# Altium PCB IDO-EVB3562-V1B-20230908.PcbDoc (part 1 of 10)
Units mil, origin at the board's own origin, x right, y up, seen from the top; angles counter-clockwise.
Board outline 5314.96 x 3543.31 mil, 4 copper layers (TOP, L2-VCC, L3-GND, BOTTOM), stack 28.8 mil thick; 747 components, 560 nets, 2514 pads, 1964 vias.
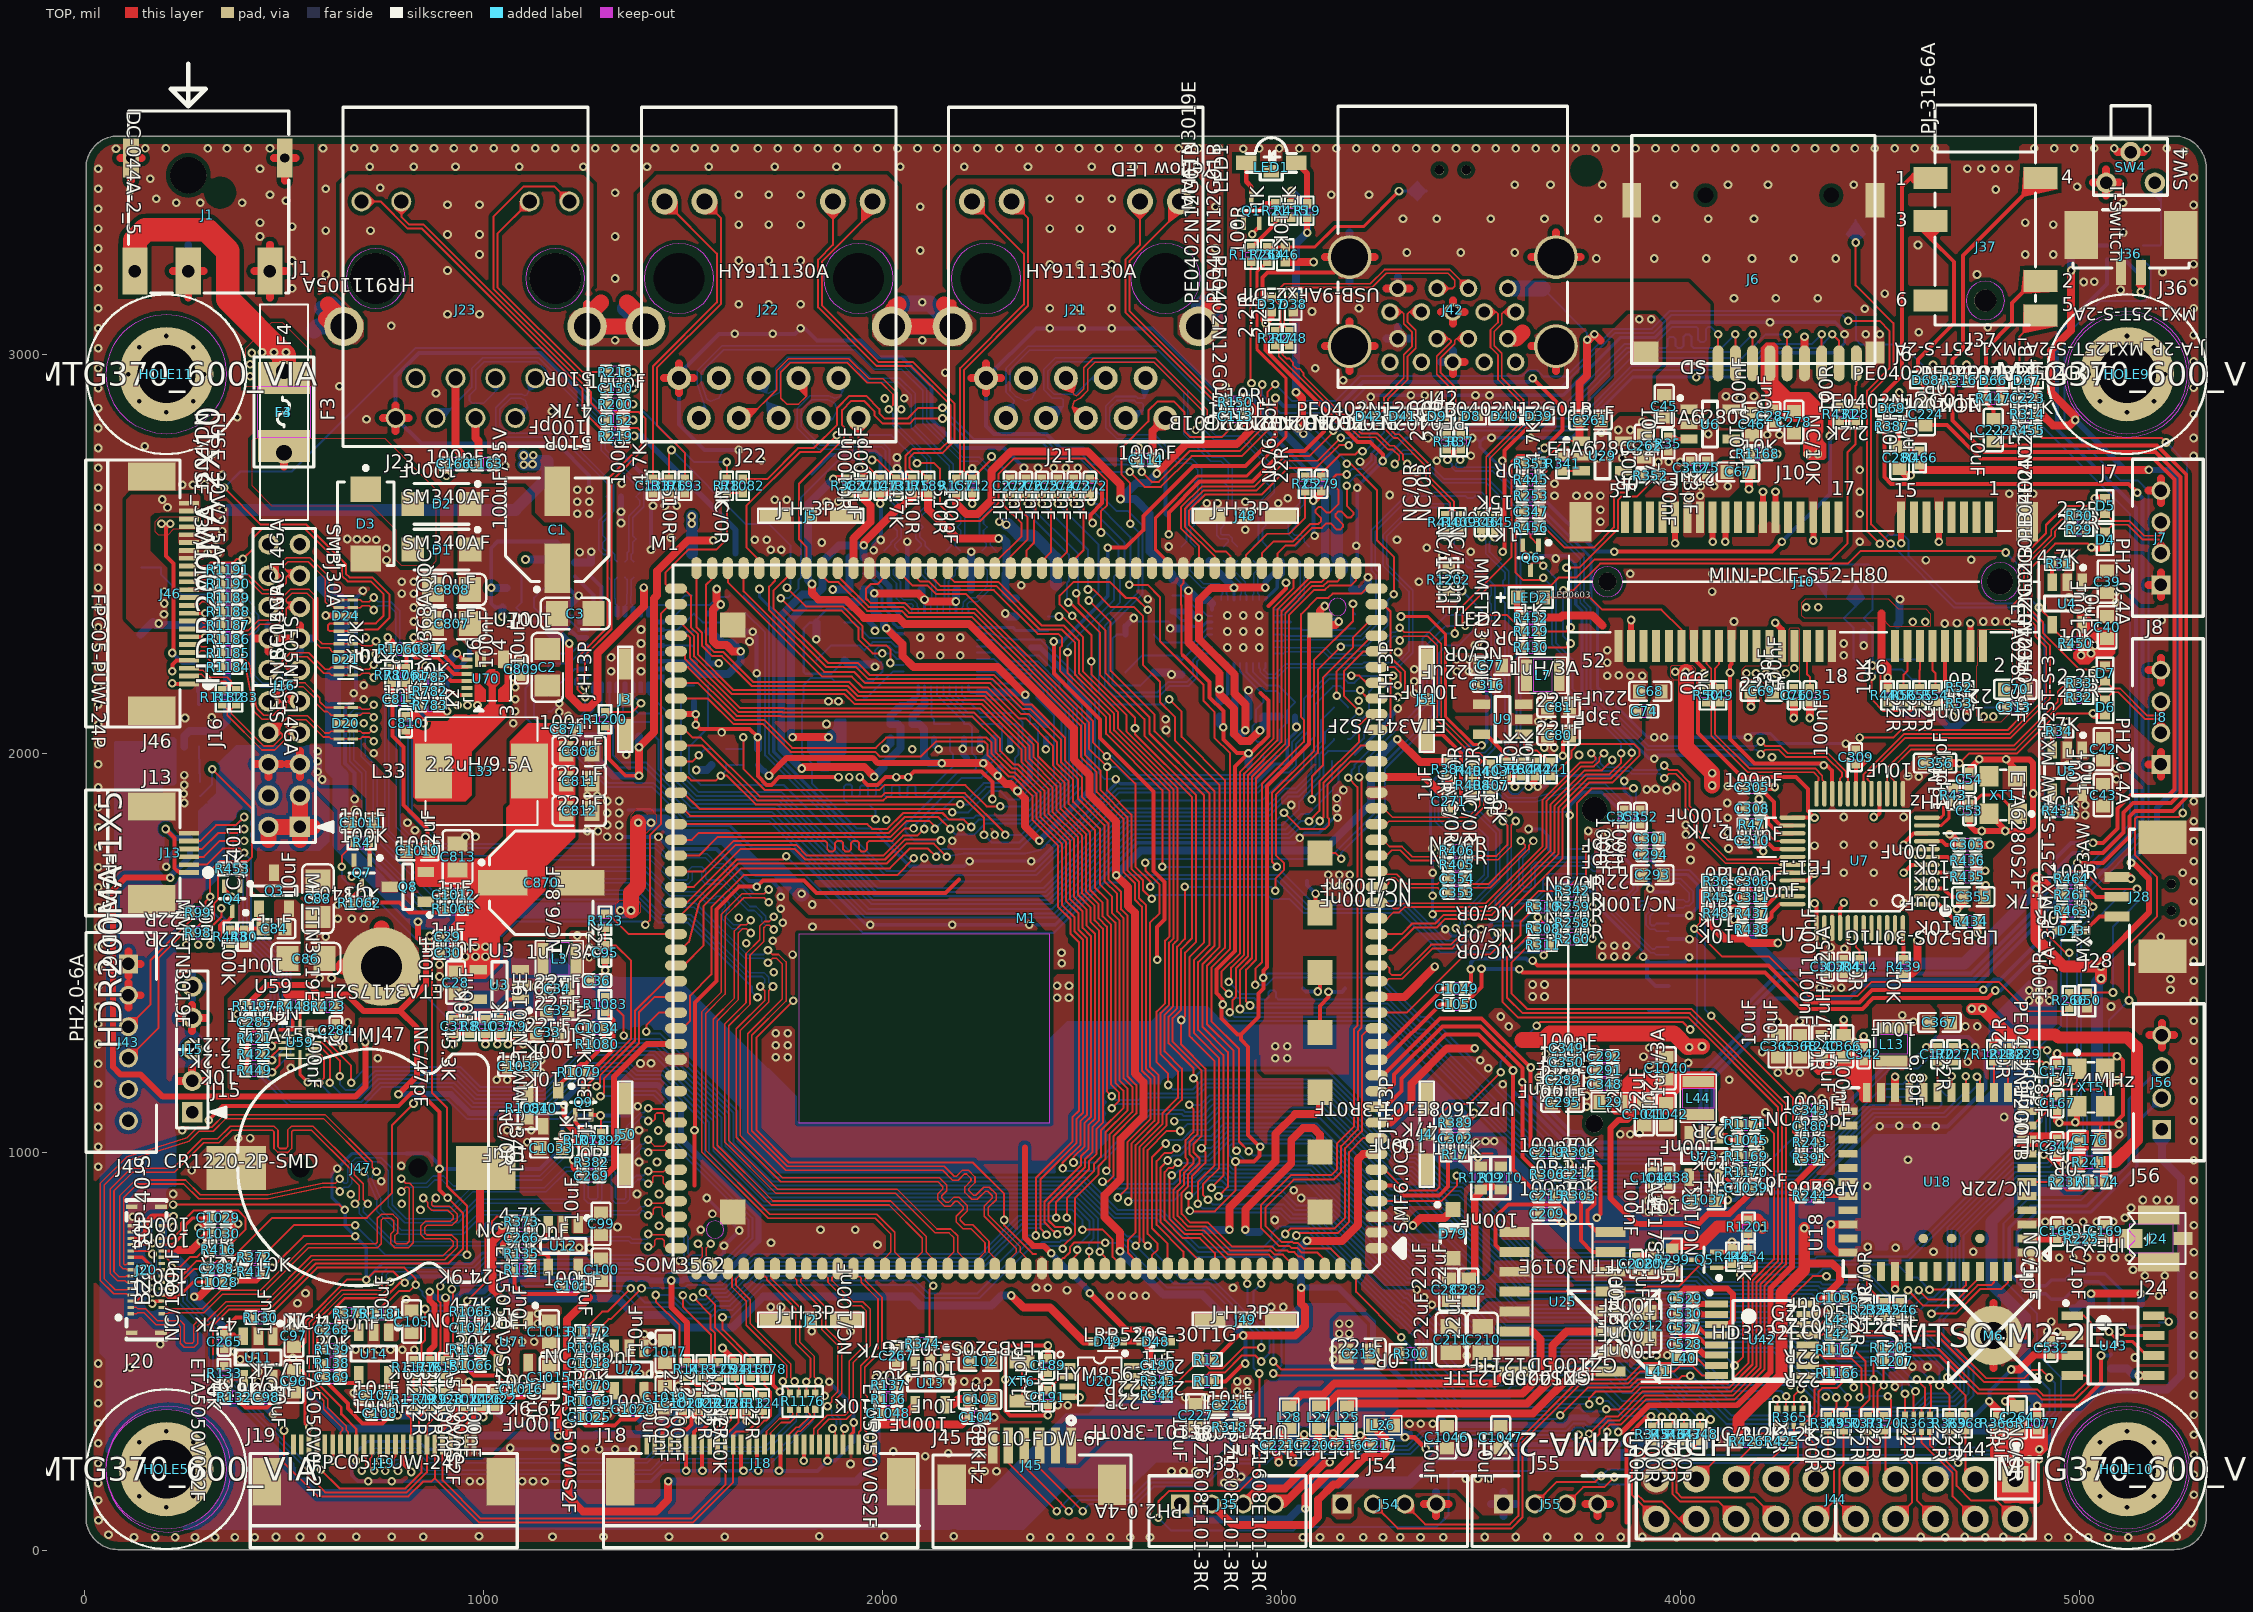
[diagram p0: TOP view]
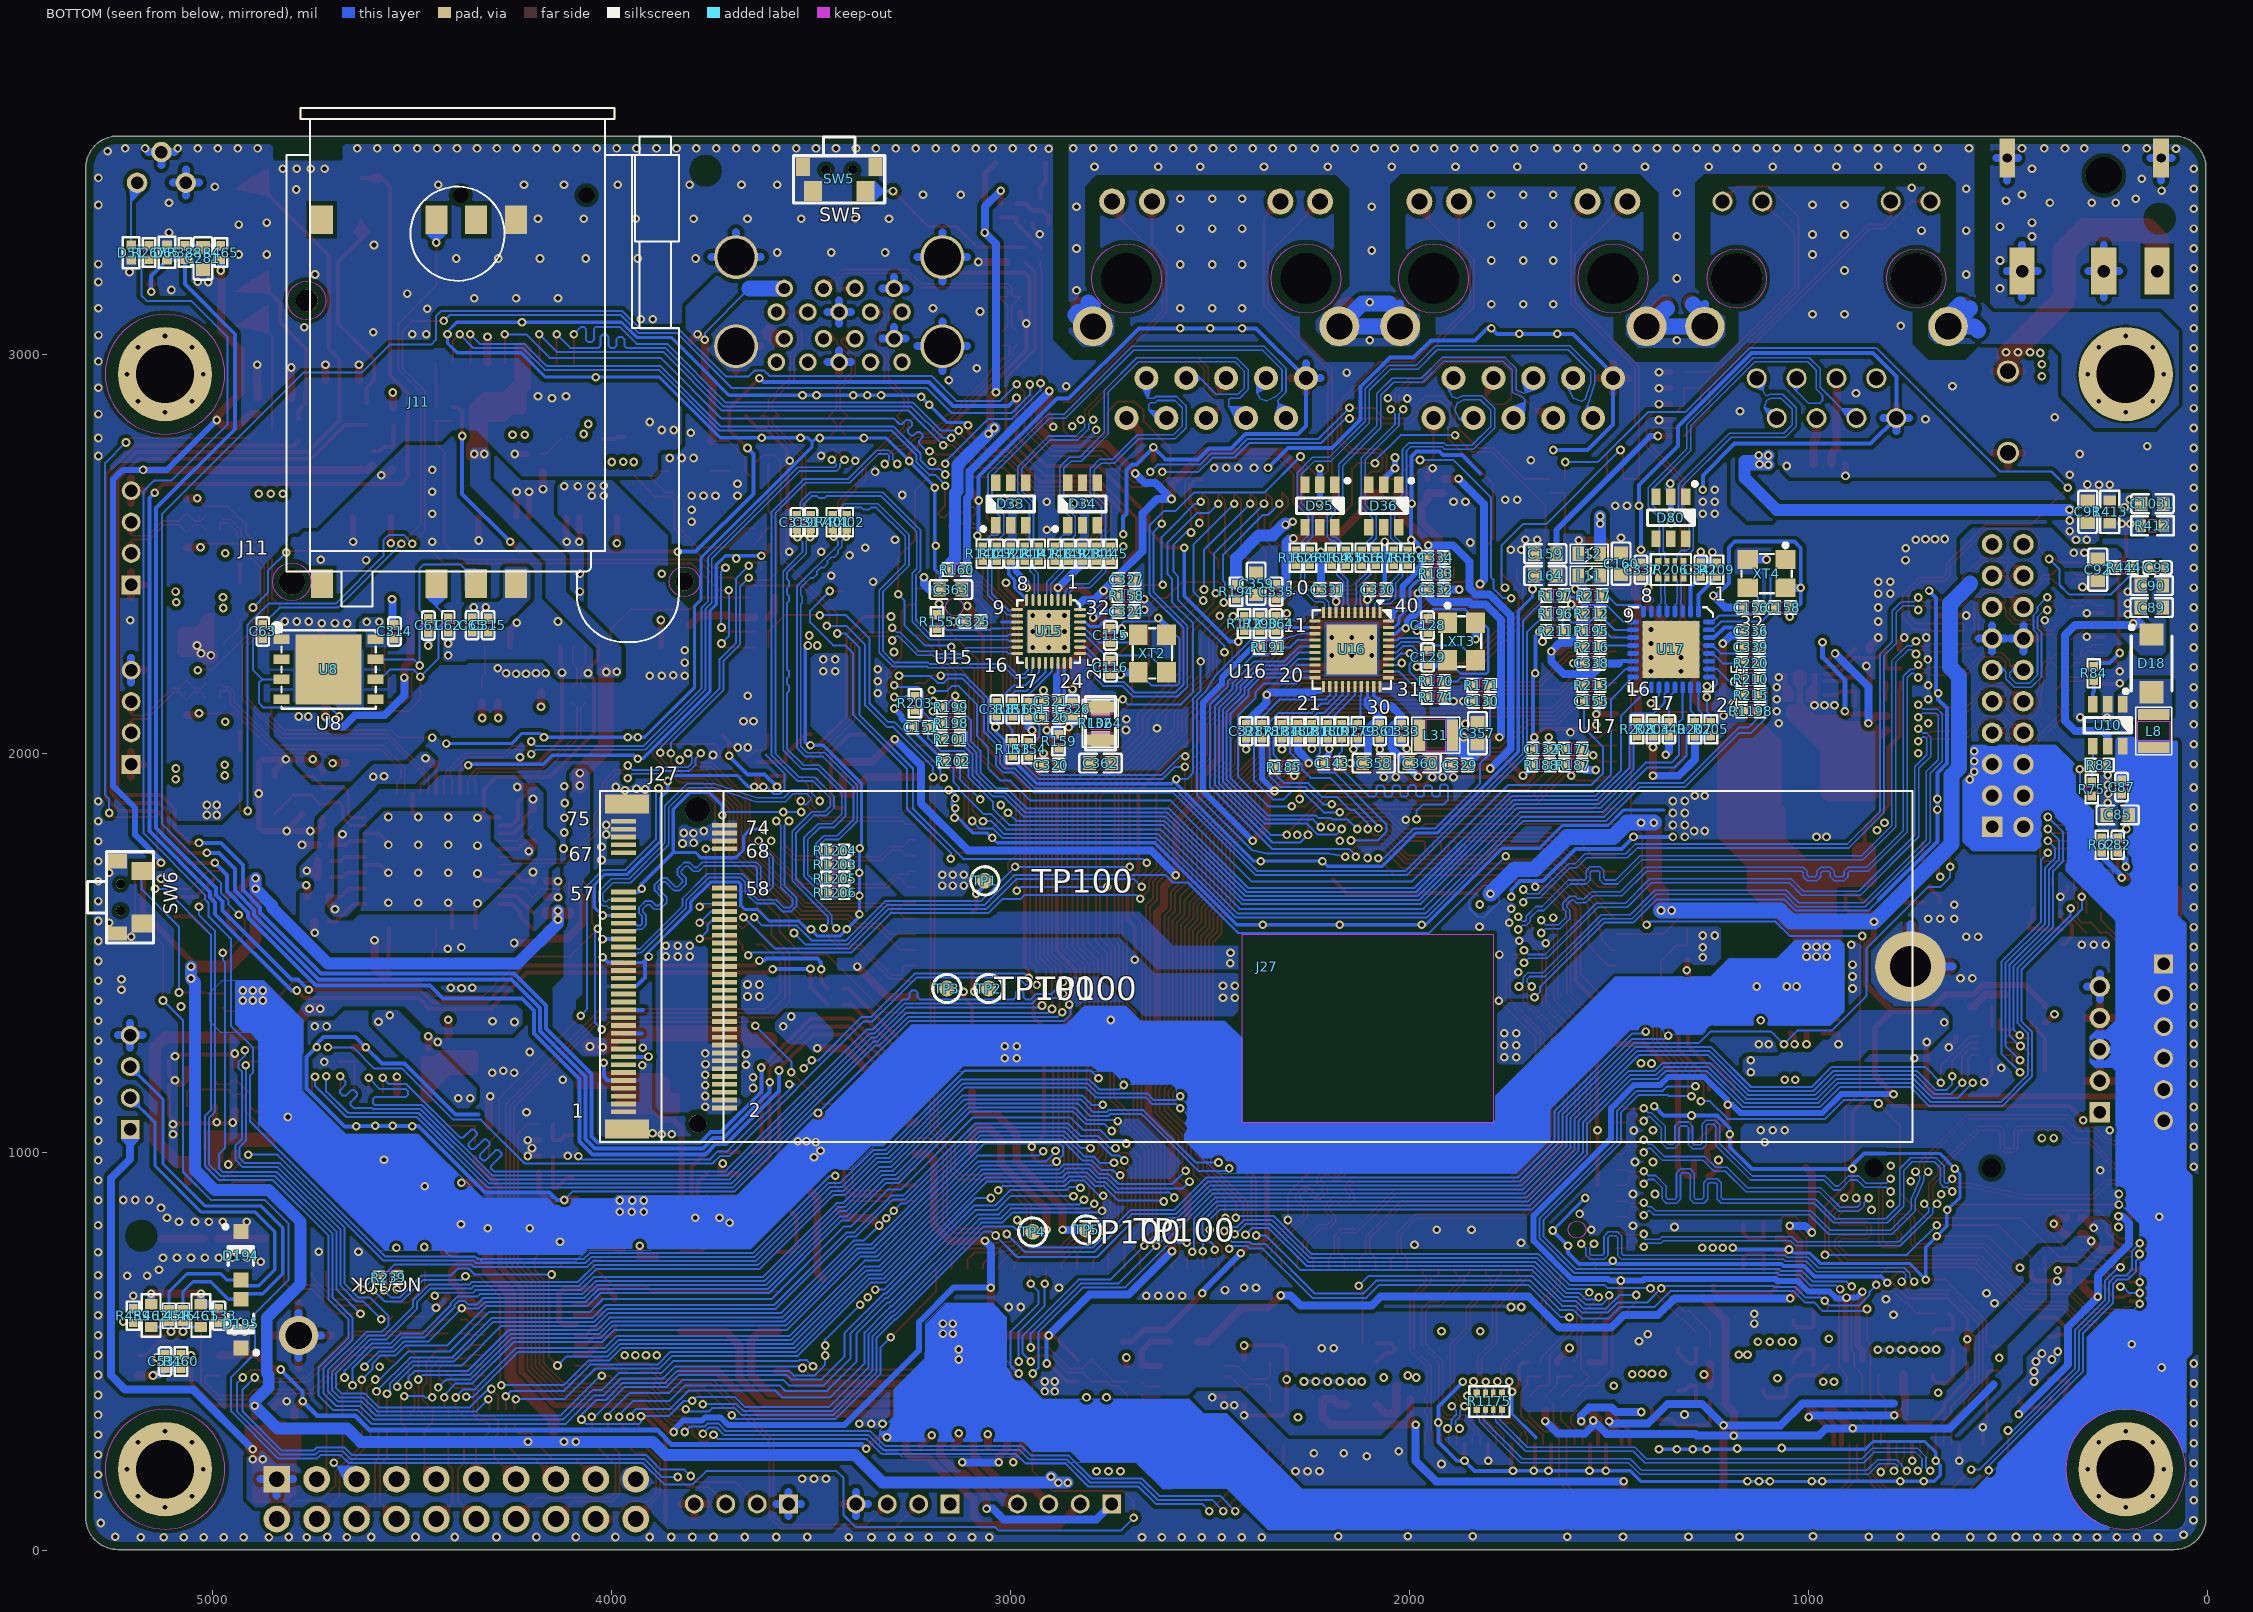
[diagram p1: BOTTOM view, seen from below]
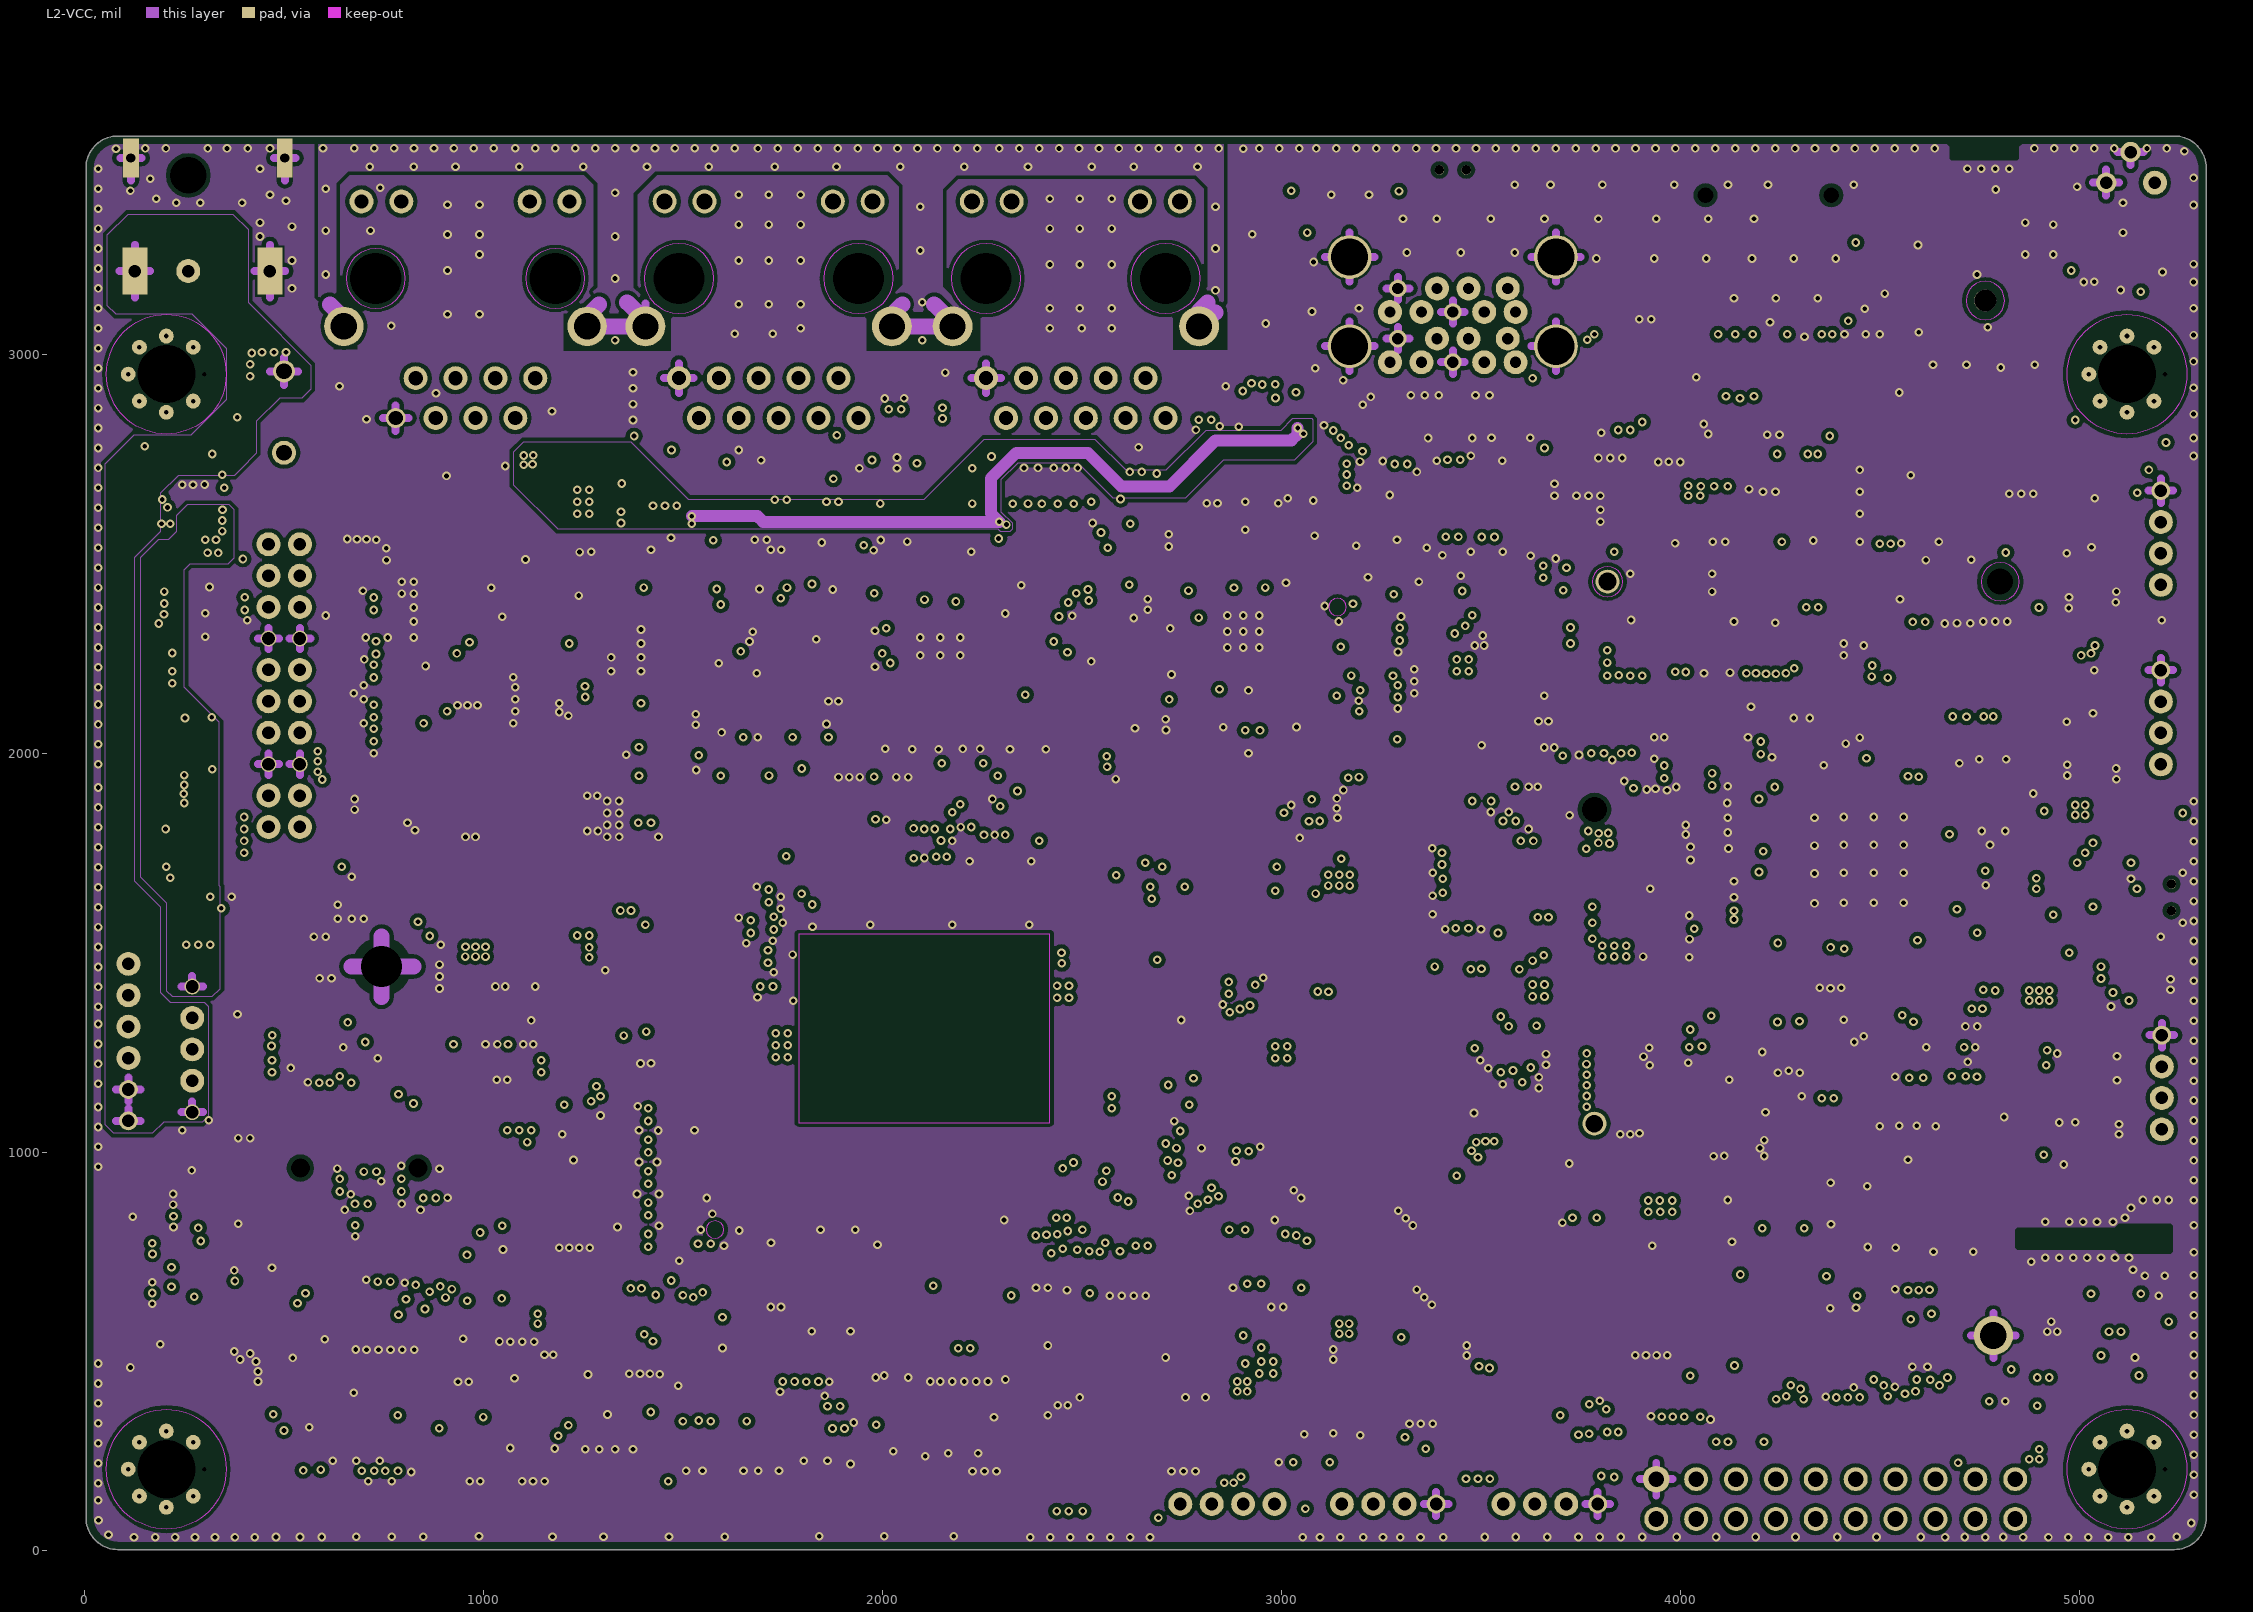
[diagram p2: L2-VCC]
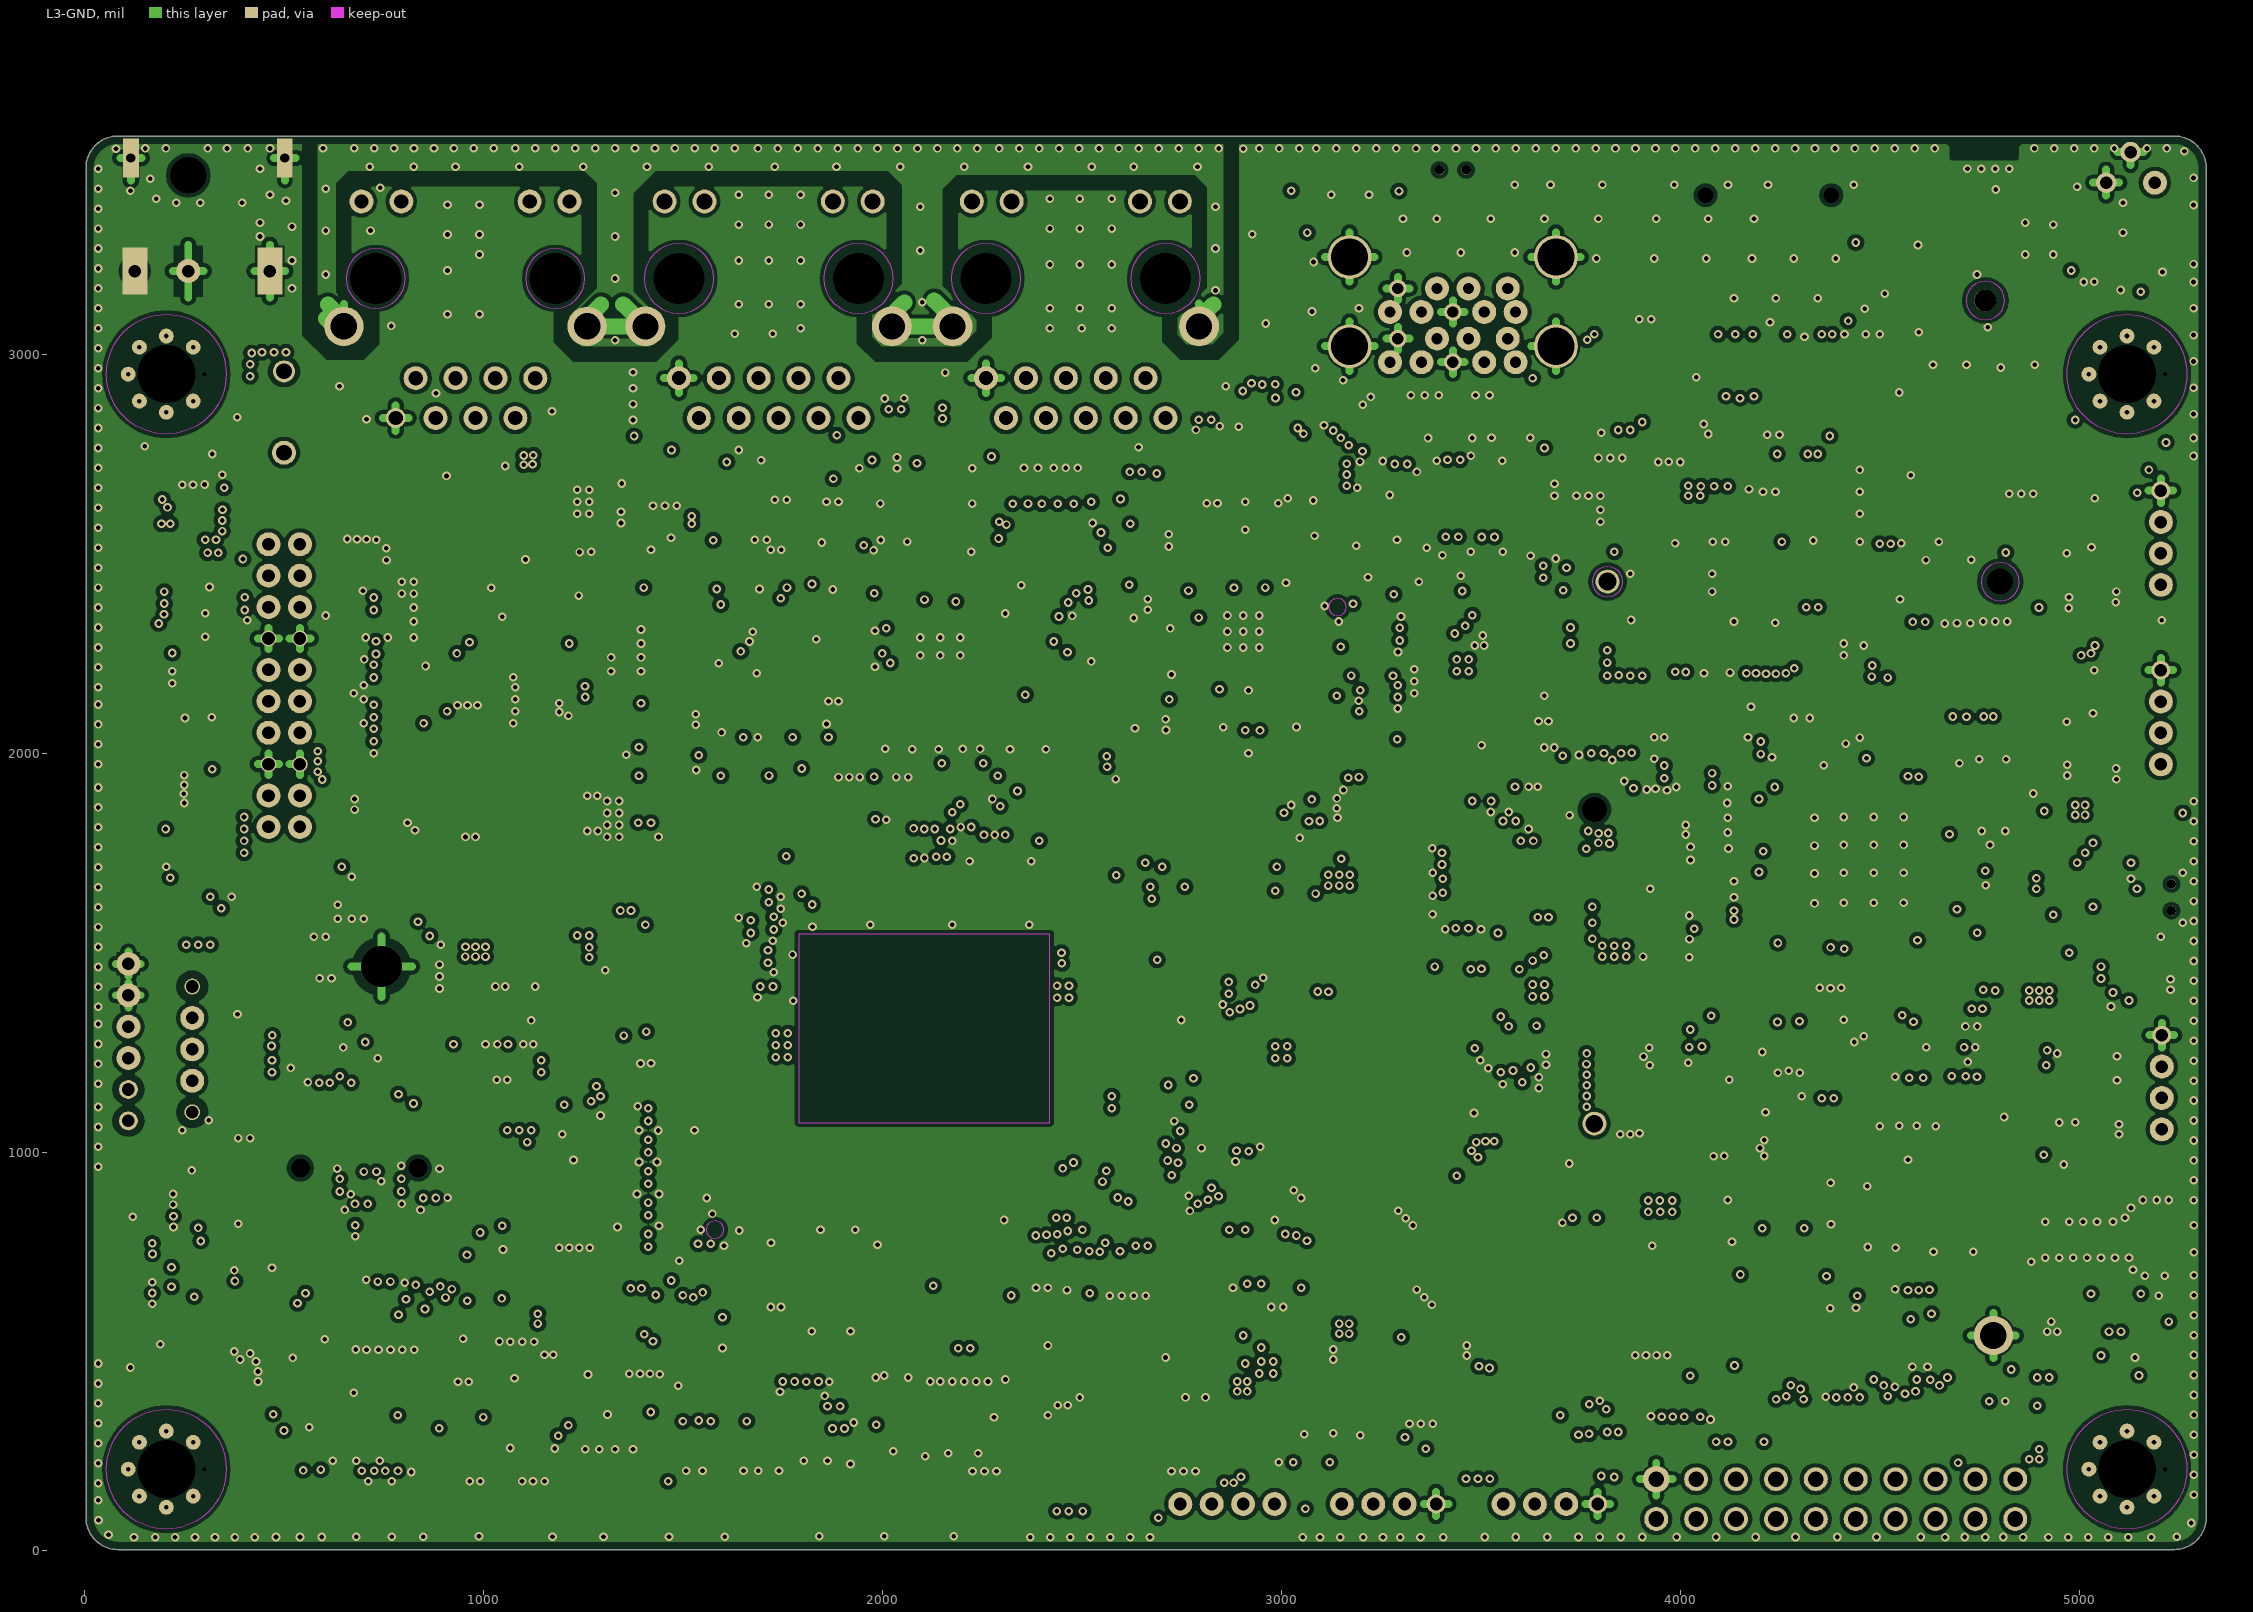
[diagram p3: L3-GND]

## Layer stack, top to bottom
Top Solder: solder mask 0.4, Solder Resist, Dk 3.5
TOP: signal copper 1.2
Dielectric 1: core 8, FR-4, Dk 4.5
L2-VCC: signal copper 1.2
Dielectric2: core 8, FR-4, Dk 4.5
L3-GND: signal copper 1.2
Dielectric3: core 8, FR-4, Dk 4.5
BOTTOM: signal copper 1.2
Bottom Solder: solder mask 0.4, Solder Resist, Dk 3.5

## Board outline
3.7,83.7 ccw(c83.7,83.7) 5238.66,3.7 ccw(c5238.66,83.7) 5318.66,3467.01 ccw(c5238.66,3467.01) 83.7,3547.01 ccw(c83.7,3467.01) 3.7,83.7

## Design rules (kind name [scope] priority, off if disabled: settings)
Clearance [All] p1: gap=10 ignorepadtopadclearanceinfootprint=FALSE except(0: Arc-Hole Track-Hole SMDPad-Hole THPad-Hole Via-Hole Fill-Hole Poly-Hole Region-Hole Text-Hole)
DiffPairsRouting [All] p1: maxlimit=10 minlimit=10 mostfreqgap=10 toplayer_minwidth=15 toplayer_maxwidth=15 toplayer_prefwidth=15 midlayer1_minwidth=15 midlayer1_maxwidth=15 midlayer1_prefwidth=15 midlayer2_minwidth=15 midlayer2_maxwidth=15 midlayer2_prefwidth=15 bottomlayer_minwidth=15 bottomlayer_maxwidth=15 bottomlayer_prefwidth=15 maxuncoupledlength=500
PlaneConnect [All] p1: planeconnectstyle=Direct reliefexpansion=20 reliefentries=4 reliefconductorwidth=10 reliefairgap=10
PolygonConnect [All] p1: connectstyle=Direct reliefconductorwidth=10 reliefentries=4 polygonreliefangle="90 Angle" airgapwidth=10
RoutingVias [All] p1: holewidth=28 width=50 viastyle="Through Hole" minholewidth=28 minwidth=50 maxholewidth=28 maxwidth=50
SolderMaskExpansion [All] p1: expansion=4 istentingtop=FALSE
Width [All] p1: maxlimit=10 minlimit=10 preferedwidth=10 impedanceprofiledriven=TRUE minimp=78.270000 maximp=78.270000 favimp=78.270000
28 further rules are at their usual default settings.

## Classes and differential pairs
net class GND0: GND
differential pair DIFFPAIR6: +USB30_OTG0_SSTXN/PCIE20_TXDN -USB30_OTG0_SSTXP/PCIE20_TXDP
differential pair DIFFPAIR7: +USB30_OTG0_SSRXN/PCIE20_RXDN -USB30_OTG0_SSRXP/PCIE20_RXDP
differential pair DIFFPAIR5: +USB30_OTG0_DM -USB30_OTG0_DP
differential pair DIFFPAIR54: +USB20_HOST1_DM -USB20_HOST1_DP
differential pair USB_PCIE_TX: +USB_PCIE_TXN -USB_PCIE_TXP
differential pair USB_PCIE_RX: +USB_PCIE_RXN -USB_PCIE_RXP
differential pair DIFFPAIR4: +USB_OTG_SSTXN -USB_OTG_SSTXP
differential pair DIFFPAIR2: +USB_OTG_SSRXN -USB_OTG_SSRXP
differential pair DIFFPAIR3: +USB_OTG_DM -USB_OTG_DP
differential pair DIFFPAIR17: +TXN -TXP
differential pair T: +TN -TP
differential pair DIFFPAIR18: +RXN -RXP
differential pair R: +RN -RP
differential pair DIFFPAIR35: +REFCLKN_100M_RJ45 -REFCLKP_100M_RJ45
differential pair DIFFPAIR31: +PHY2_MDI3- -PHY2_MDI3+
differential pair DIFFPAIR32: +PHY2_MDI2- -PHY2_MDI2+
differential pair DIFFPAIR33: +PHY2_MDI1- -PHY2_MDI1+
differential pair DIFFPAIR34: +PHY2_MDI0- -PHY2_MDI0+
differential pair DIFFPAIR30: +PHY2_MDI_3- -PHY2_MDI_3+
differential pair DIFFPAIR29: +PHY2_MDI_2- -PHY2_MDI_2+
differential pair DIFFPAIR28: +PHY2_MDI_1- -PHY2_MDI_1+
differential pair DIFFPAIR27: +PHY2_MDI_0- -PHY2_MDI_0+
differential pair DIFFPAIR26: +PHY0_MDI3- -PHY0_MDI3+
differential pair DIFFPAIR25: +PHY0_MDI2- -PHY0_MDI2+
differential pair DIFFPAIR24: +PHY0_MDI1- -PHY0_MDI1+
differential pair DIFFPAIR23: +PHY0_MDI0- -PHY0_MDI0+
differential pair DIFFPAIR11: +PCIE20_TXDN -PCIE20_TXDP
differential pair DIFFPAIR10: +PCIE20_RXDN -PCIE20_RXDP
differential pair DIFFPAIR37: +PCIE20_REFCLKN_ -PCIE20_REFCLKP_
differential pair DIFFPAIR36: +PCIE20_REFCLKN -PCIE20_REFCLKP
differential pair DIFFPAIR8: +PCIE20_0_TXN -PCIE20_0_TXP
differential pair DIFFPAIR9: +PCIE_0_RXN -PCIE_0_RXP
differential pair DIFFPAIR55: +MIPI_TX_D3N -MIPI_TX_D3P
differential pair DIFFPAIR56: +MIPI_TX_D2N -MIPI_TX_D2P
differential pair DIFFPAIR58: +MIPI_TX_D1N -MIPI_TX_D1P
differential pair DIFFPAIR59: +MIPI_TX_D0N -MIPI_TX_D0P
differential pair DIFFPAIR57: +MIPI_TX_CLKN -MIPI_TX_CLKP
differential pair DIFFPAIR38: +MIPI_DSI_TX_D3N/LVDS_TX_D3N -MIPI_DSI_TX_D3P/LVDS_TX_D3P
differential pair DIFFPAIR40: +MIPI_DSI_TX_D2N/LVDS_TX_D2N -MIPI_DSI_TX_D2P/LVDS_TX_D2P
differential pair DIFFPAIR41: +MIPI_DSI_TX_D1N/LVDS_TX_D1N -MIPI_DSI_TX_D1P/LVDS_TX_D1P
differential pair DIFFPAIR42: +MIPI_DSI_TX_D0N/LVDS_TX_D0N -MIPI_DSI_TX_D0P/LVDS_TX_D0P
differential pair DIFFPAIR39: +MIPI_DSI_TX_CLKN/LVDS_TX_CLKN -MIPI_DSI_TX_CLKP/LVDS_TX_CLKP
differential pair DIFFPAIR61: +MIPI_CSI2_RX0_D3N -MIPI_CSI2_RX0_D3P
differential pair DIFFPAIR60: +MIPI_CSI2_RX0_D2N -MIPI_CSI2_RX0_D2P
differential pair DIFFPAIR62: +MIPI_CSI1_RX0_D3N -MIPI_CSI1_RX0_D3P
differential pair DIFFPAIR63: +MIPI_CSI1_RX0_D2N -MIPI_CSI1_RX0_D2P
differential pair DIFFPAIR44: +MIPI_CSI_RX1_D3N -MIPI_CSI_RX1_D3P
differential pair DIFFPAIR43: +MIPI_CSI_RX1_D2N -MIPI_CSI_RX1_D2P
differential pair DIFFPAIR45: +MIPI_CSI_RX1_D1N -MIPI_CSI_RX1_D1P
differential pair DIFFPAIR46: +MIPI_CSI_RX1_D0N -MIPI_CSI_RX1_D0P
differential pair DIFFPAIR47: +MIPI_CSI_RX1_CLK0N -MIPI_CSI_RX1_CLK0P
differential pair DIFFPAIR48: +MIPI_CSI_RX0_D3N -MIPI_CSI_RX0_D3P
differential pair DIFFPAIR49: +MIPI_CSI_RX0_D2N -MIPI_CSI_RX0_D2P
differential pair DIFFPAIR51: +MIPI_CSI_RX0_D1N -MIPI_CSI_RX0_D1P
differential pair DIFFPAIR52: +MIPI_CSI_RX0_D0N -MIPI_CSI_RX0_D0P
differential pair DIFFPAIR50: +MIPI_CSI_RX0_CLK1N -MIPI_CSI_RX0_CLK1P
differential pair DIFFPAIR53: +MIPI_CSI_RX0_CLK0N -MIPI_CSI_RX0_CLK0P
differential pair DIFFPAIR22: +LAN0_D- -LAN0_D+
differential pair DIFFPAIR21: +LAN0_C- -LAN0_C+
differential pair DIFFPAIR20: +LAN0_B- -LAN0_B+
differential pair DIFFPAIR19: +LAN0_A- -LAN0_A+
differential pair DIFFPAIR15: +HUB_DM4_2 -HUB_DP4_2
differential pair DIFFPAIR14: +HUB_DM4 -HUB_DP4
differential pair DIFFPAIR16: +HUB_DM3_2 -HUB_DP3_2
differential pair DIFFPAIR13: +HUB_DM3 -HUB_DP3
differential pair DIFFPAIR0: +HUB_DM2_2 -HUB_DP2_2
differential pair DIFFPAIR1: +HUB_DM2 -HUB_DP2
differential pair DIFFPAIR12: +HUB_DM1 -HUB_DP1
differential pair 4G_D: +4G_DM -4G_DP

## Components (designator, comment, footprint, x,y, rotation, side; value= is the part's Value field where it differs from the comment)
C1 "C-AL-SMD_CAPAE660X770_100UF/35V" ASSEMBLY_TOP#1 1185,2560 r90 top
C2 "C-1206_C1206_10UF" DISPLAY_TOP#1 1160,2215 r90 top
C3 "C-1206_C1206_10UF" DISPLAY_TOP#1 1230,2350 r180 top
C28 "C-0603_C0603_10UF" DISPLAY_TOP#2 930,1425 r90 top
C29 "C-0402_C0402_1UF" DISPLAY_TOP#3 910,1540.01 r0 top
C30 "C-0402_C0402_100NF" DISPLAY_TOP#3 910,1500.01 r0 top
C31 "C-0402_C0402_NC/47PF" DISPLAY_TOP#3 924.99,1315 r270 top
C32 "C-0603_C0603_22UF" DISPLAY_TOP#2 1185,1355 r0 top
C33 "C-0603_C0603_22UF" DISPLAY_TOP#2 1160,1300 r0 top
C34 "C-0603_C0603_22UF" DISPLAY_TOP#2 1185,1410 r0 top
C36 "C-0402_C0402_100NF" DISPLAY_TOP#3 1285,1430 r180 top
C37 "C-0402_C0402_100NF" DISPLAY_TOP#3 1045.01,1315 r90 top
C39 "C-0603_C0603_10UF" DISPLAY_TOP#2 5070,2430 r270 top
C40 "C-0603_C0603_10UF" DISPLAY_TOP#2 5070,2315 r90 top
C42 "C-0603_C0603_10UF" DISPLAY_TOP#2 5060,2010 r270 top
C43 "C-0603_C0603_10UF" DISPLAY_TOP#2 5060,1895 r90 top
C45 "C-0603_C0603_10UF" ASSEMBLY_TOP#2 3960,2870 r270 top
C46 "C-0603_C0603_10UF" ASSEMBLY_TOP#2 4180,2825 r270 top
C53 "C-0402_C0402_18PF" ASSEMBLY_TOP#3 4725.01,1855 r90 top
C54 "C-0402_C0402_18PF" ASSEMBLY_TOP#3 4725.01,1935 r90 top
C61 "C-0402_C0402_33PF" ASSEMBLY_BOTTOM#1 4460,2320 r90 bottom
C62 "C-0402_C0402_33PF" ASSEMBLY_BOTTOM#1 4410,2321 r90 bottom
C63 "C-0402_C0402_33PF" ASSEMBLY_BOTTOM#1 4875,2305 r90 bottom
C65 "C-0402_C0402_100PF" ASSEMBLY_BOTTOM#1 4350,2321 r90 bottom
C67 "C-0603_C0603_22UF" ASSEMBLY_TOP#2 4145,2705 r180 top
C68 "C-0603_C0603_22UF" ASSEMBLY_TOP#2 3925,2155 r180 top
C69 "C-0603_C0603_22UF" ASSEMBLY_TOP#2 4205,2155 r0 top
C70 "C-0603_C0603_22UF" ASSEMBLY_TOP#2 4840,2160 r180 top
C74 "C-0402_C0402_33PF" ASSEMBLY_TOP#3 3910,2105 r180 top
C75 "C-0402_C0402_33PF" ASSEMBLY_TOP#3 4064.99,2715 r270 top
C76 "C-0402_C0402_33PF" ASSEMBLY_TOP#3 4285.01,2145 r90 top
C77 "C-0603_C0603_22UF" DISPLAY_TOP#2 3525,2220 r180 top
C79 "C-0402_C0402_47PF" DISPLAY_TOP#3 3564.99,1960 r270 top
C80 "C-0603_C0603_22UF" DISPLAY_TOP#2 3695,2045 r0 top
C81 "C-0603_C0603_22UF" DISPLAY_TOP#2 3695,2115 r0 top
C82 "C-0402_C0402_1UF" DISPLAY_BOTTOM#1 225,1770 r90 bottom
C84 "C-0603_C0603_1UF" DISPLAY_TOP#2 475,1560 r0 top
C85 "C-0603_C0603_22UF" DISPLAY_BOTTOM#2 225,1845 r0 bottom
C86 "C-1206_C1206_10UF" DISPLAY_TOP#1 555,1485 r180 top
C87 "C-0402_C0402_100NF" DISPLAY_BOTTOM#1 215,1915 r90 bottom
C88 "C-1206_C1206_10UF" DISPLAY_TOP#1 585,1635 r90 top
C89 "C-0603_C0603_1UF" DISPLAY_BOTTOM#3 140,2365 r0 bottom
C90 "C-0603_C0603_1UF" DISPLAY_BOTTOM#3 140,2420 r0 bottom
C91 "C-0603_C0603_10UF" DISPLAY_BOTTOM#3 300,2605 r270 bottom
C92 "C-0603_C0603_10UF" DISPLAY_BOTTOM#3 275,2460 r90 bottom
C93 "C-0402_C0402_1UF" DISPLAY_BOTTOM#1 125,2465.01 r0 bottom
C94 "C-0402_C0402_100NF" DISPLAY_TOP#3 1630,455 r270 top
C95 "C-0402_C0402_NC/6.8PF" DISPLAY_TOP#3 1305,1500 r90 top
C96 "C-0603_C0603_10UF" DISPLAY_TOP#2 525,425 r270 top
C97 "C-0603_C0603_10UF" DISPLAY_TOP#2 525,540 r90 top
C98 "C-0402_C0402_100NF" DISPLAY_TOP#3 455,385 r0 top
C99 "C-0603_C0603_10UF" DISPLAY_TOP#2 1295,820 r90 top
C100 "C-0603_C0603_10UF" DISPLAY_TOP#2 1295,705 r270 top
C101 "C-0402_C0402_100NF" DISPLAY_TOP#3 1220,664.99 r0 top
C102 "C-0603_C0603_10UF" DISPLAY_TOP#2 2245,475 r180 top
C103 "C-0603_C0603_10UF" DISPLAY_TOP#2 2245,380 r180 top
C104 "C-0402_C0402_100NF" DISPLAY_TOP#3 2235,335 r180 top
C105 "C-0603_C0603_10UF" DISPLAY_TOP#2 820,575 r90 top
C107 "C-0603_C0603_10UF" DISPLAY_TOP#2 730,390 r0 top
C108 "C-0402_C0402_100NF" DISPLAY_TOP#3 740,345 r0 top
C112 "C-0402_C0402_100PF" DISPLAY_TOP#3 2224.99,2670 r270 top
C113 "C-0402_C0402_100PF" DISPLAY_TOP#3 2885,2845 r0 top
C114 "C-0402_C0402_100NF" DISPLAY_TOP#3 2660,2735 r0 top
C115 "C-0402_C0402_18PF" DISPLAY_BOTTOM#1 2749.99,2295 r90 bottom
C116 "C-0402_C0402_18PF" DISPLAY_BOTTOM#1 2750.01,2215 r270 bottom
C126 "C-0402_C0402_NC/1UF" DISPLAY_BOTTOM#1 2900,2090.01 r0 bottom
C128 "C-0402_C0402_18PF" DISPLAY_BOTTOM#1 1955.01,2320 r270 bottom
C129 "C-0402_C0402_18PF" DISPLAY_BOTTOM#1 1954.99,2240 r90 bottom
C130 "C-0402_C0402_NC/6.8PF" DISPLAY_BOTTOM#4 1820,2130.01 r0 bottom
C131 "C-0402_C0402_100PF" DISPLAY_TOP#3 2035.01,2670 r90 top
C132 "C-0402_C0402_NC/2.2PF" DISPLAY_BOTTOM#4 1670,2009.99 r0 bottom
C133 "C-0402_C0402_100PF" DISPLAY_TOP#3 1425.01,2670 r90 top
C143 "C-0402_C0402_NC/2.2PF" DISPLAY_BOTTOM#4 2195,1975 r0 bottom
C147 "C-0402_C0402_100NF" DISPLAY_TOP#3 1995,2670 r90 top
C150 "C-0402_C0402_100PF" DISPLAY_TOP#3 1330,2915 r0 top
C151 "C-0402_C0402_NC/6.8PF" DISPLAY_BOTTOM#4 3225,2065 r0 bottom
C152 "C-0402_C0402_100PF" DISPLAY_TOP#3 1330,2835 r180 top
C155 "C-0402_C0402_NC/6.8PF" DISPLAY_BOTTOM#1 1545,2130 r0 bottom
C156 "C-0402_C0402_18PF" DISPLAY_BOTTOM#1 1145,2365.01 r0 bottom
C158 "C-0402_C0402_18PF" DISPLAY_BOTTOM#1 1065,2365.01 r0 bottom
C159 "C-0603_C0603_10UF" DISPLAY_BOTTOM#2 1660,2500 r0 bottom
C160 "C-0603_C0603_10UF" DISPLAY_BOTTOM#3 1470,2475 r270 bottom
C163 "C-0402_C0402_100NF" DISPLAY_TOP#3 1005,2725.01 r180 top
C164 "C-0603_C0603_10UF" DISPLAY_BOTTOM#2 1660,2445 r0 bottom
C166 "C-0402_C0402_100NF" DISPLAY_TOP#3 925,2724.99 r0 top
C167 "C-0402_C0402_18PF" DISPLAY_TOP#3 4945.01,1122 r90 top
C168 "C-0402_C0402_NC/1PF" DISPLAY_TOP#3 4944.99,800.99 r270 top
C169 "C-0402_C0402_NC/1PF" DISPLAY_TOP#3 5064.99,800.99 r270 top
C170 "C-0402_C0402_6.8PF" DISPLAY_TOP#3 4644.99,1245 r270 top
C171 "C-0402_C0402_18PF" DISPLAY_TOP#3 4944.99,1202 r270 top
C176 "C-0603_C0603_22UF" DISPLAY_TOP#2 5025,1030 r180 top
C180 "C-0402_C0402_NC/6.8PF" DISPLAY_TOP#3 4325,1064.99 r0 top
C189 "C-0402_C0402_11PF" DISPLAY_TOP#3 2414.99,465 r270 top
C190 "C-0402_C0402_1UF" DISPLAY_TOP#3 2690,465 r0 top
C191 "C-0402_C0402_11PF" DISPLAY_TOP#3 2415.01,385 r90 top
C207 "C-0402_C0402_1UF" ASSEMBLY_TOP#3 3929.99,720 r270 top
C208 "C-0402_C0402_100NF" ASSEMBLY_TOP#3 3889.99,719.99 r270 top
C209 "C-0402_C0402_100NF" DISPLAY_TOP#3 3665,845 r180 top
C210 "C-0805_C0805_22UF" DISPLAY_TOP#4 3505,530 r90 top
C211 "C-0805_C0805_22UF" DISPLAY_TOP#4 3425,530 r90 top
C212 "C-0805_C0805_22UF" ASSEMBLY_TOP#4 3915,565 r90 top
C213 "C-0805_C0805_22UF" DISPLAY_TOP#4 3195,495 r0 top
C214 "C-0402_C0402_1UF" DISPLAY_TOP#3 3745,945 r0 top
C215 "C-0402_C0402_100NF" DISPLAY_TOP#3 3665,890 r0 top
C216 "C-0402_C0402_1NF" DISPLAY_TOP#3 3160,265.01 r180 top
C217 "C-0402_C0402_1NF" DISPLAY_TOP#3 3245,265.01 r180 top
C219 "C-0402_C0402_100NF" DISPLAY_TOP#3 3665,1000 r0 top
C220 "C-0402_C0402_1NF" DISPLAY_TOP#3 3075,265.01 r180 top
C221 "C-0402_C0402_1NF" DISPLAY_TOP#3 2990,265.01 r180 top
C222 "C-0603_C0603_10UF" ASSEMBLY_TOP#2 4785,2810 r270 top
C223 "C-0402_C0402_NC/100NF" ASSEMBLY_TOP#3 4870,2890.01 r180 top
C224 "C-0603_C0603_10UF" ASSEMBLY_TOP#2 4615,2850 r270 top
C226 "C-0603_C0603_10UF" DISPLAY_TOP#2 2870,365 r0 top
C227 "C-0603_C0603_10UF" DISPLAY_TOP#2 2785,340 r270 top
C261 "C-0603_C0603_10UF" DISPLAY_TOP#2 3775,2835 r0 top
C262 "C-0603_C0603_10UF" ASSEMBLY_TOP#2 3910,2770 r270 top
C264 "C-0603_C0603_10UF" DISPLAY_TOP#2 4845,335 r270 top
C265 "C-0402_C0402_NC/100NF" DISPLAY_TOP#3 350,525 r90 top
C266 "C-0402_C0402_NC/100NF" DISPLAY_TOP#3 1095,784.99 r0 top
C267 "C-0402_C0402_NC/100NF" DISPLAY_TOP#3 2035,490 r90 top
C268 "C-0402_C0402_NC/100NF" DISPLAY_TOP#3 620,554.99 r0 top
C269 "C-0402_C0402_1UF" DISPLAY_TOP#3 1270,940 r0 top
C270 "C-0402_C0402_1UF" DISPLAY_TOP#3 1954.99,2670 r270 top
C271 "C-0402_C0402_1UF" DISPLAY_TOP#3 3420,1880 r90 top
C272 "C-0402_C0402_1NF" DISPLAY_TOP#3 2519.99,2670 r270 top
C273 "C-0402_C0402_1NF" DISPLAY_TOP#3 2479.99,2670 r270 top
C274 "C-0402_C0402_1NF" DISPLAY_TOP#3 2439.99,2670 r270 top
C275 "C-0402_C0402_1NF" DISPLAY_TOP#3 2399.99,2670 r270 top
C276 "C-0402_C0402_1NF" DISPLAY_TOP#3 2359.99,2670 r270 top
C277 "C-0402_C0402_1NF" DISPLAY_TOP#3 2319.99,2670 r270 top
C278 "C-0603_C0603_10UF" ASSEMBLY_TOP#2 4285,2830 r90 top
C279 "C-0402_C0402_NC/6.8PF" DISPLAY_TOP#3 3100.01,2675 r90 top
C280 "C-0603_C0603_10UF" DISPLAY_TOP#2 4550,2740 r90 top
C281 "C-0603_C0603_10UF" DISPLAY_TOP#2 5025,3240 r90 bottom
C282 "C-0603_C0603_22UF" DISPLAY_TOP#2 3470,655 r90 top
C283 "C-0603_C0603_22UF" DISPLAY_TOP#2 3420,655 r90 top
C284 "C-0402_C0402_100NF" DISPLAY_TOP#3 630,1305 r270 top
C285 "C-0402_C0402_100NF" DISPLAY_TOP#3 425,1324.99 r0 top
C287 "C-0402_C0402_100NF" ASSEMBLY_TOP#3 4235.01,2845 r90 top
C288 "C-0402_C0402_100NF" DISPLAY_TOP#3 330,707.01 r180 top
C289 "C-0603_C0603_22UF" DISPLAY_TOP#2 3705,1180 r0 top
C291 "C-0402_C0402_33PF" ASSEMBLY_TOP#3 3810,1205.01 r180 top
C292 "C-0402_C0402_33PF" ASSEMBLY_TOP#3 3810,1240.01 r180 top
C293 "C-0603_C0603_22UF" DISPLAY_TOP#2 3930,1695 r180 top
C294 "C-0402_C0402_33PF" ASSEMBLY_TOP#3 3925,1745 r180 top
C295 "C-0603_C0603_22UF" DISPLAY_TOP#2 3705,1125 r0 top
C301 "C-0402_C0402_33PF" DISPLAY_TOP#3 3925,1785 r180 top
C302 "C-0402_C0402_100NF" DISPLAY_TOP#3 3436,1033.01 r180 top
C303 "C-0402_C0402_100NF" ASSEMBLY_TOP#3 4720,1770.01 r180 top
C304 "C-0402_C0402_100NF" ASSEMBLY_TOP#3 4410.01,1465 r90 top
C305 "C-0402_C0402_100NF" ASSEMBLY_TOP#3 4180,1914.99 r0 top
C306 "C-0402_C0402_100NF" ASSEMBLY_TOP#3 4180,1678.99 r0 top
C307 "C-0402_C0402_100NF" ASSEMBLY_TOP#3 4369.99,1465 r270 top
C308 "C-0402_C0402_100NF" ASSEMBLY_TOP#3 4180,1860.01 r180 top
C309 "C-0402_C0402_100NF" ASSEMBLY_TOP#3 4440.01,1990 r90 top
C310 "C-0402_C0402_100NF" ASSEMBLY_TOP#3 4180,1779.99 r0 top
C311 "C-0402_C0402_NC/100NF" ASSEMBLY_TOP#3 4180,1638.99 r0 top
C312 "C-0402_C0402_100NF" ASSEMBLY_TOP#3 4024.99,2715 r270 top
C313 "C-0402_C0402_100NF" ASSEMBLY_TOP#3 4835,2115 r180 top
C314 "C-0402_C0402_100NF" ASSEMBLY_BOTTOM#1 4545,2305 r270 bottom
C315 "C-0402_C0402_100NF" ASSEMBLY_BOTTOM#1 4310,2321 r90 bottom
C316 "C-0402_C0402_100NF" DISPLAY_TOP#3 3515,2170.01 r180 top
C317 "C-0402_C0402_100NF" DISPLAY_BOTTOM#1 3501,2579 r90 bottom
C318 "C-0402_C0402_100NF" DISPLAY_BOTTOM#1 3034.99,2110 r90 bottom
C319 "C-0402_C0402_100NF" DISPLAY_BOTTOM#1 3536,2579 r90 bottom
C320 "C-0402_C0402_100NF" DISPLAY_BOTTOM#4 2900,1969.99 r0 bottom
C321 "C-0402_C0402_100NF" DISPLAY_BOTTOM#4 2900,2129.99 r0 bottom
C322 "C-0402_C0402_100NF" DISPLAY_BOTTOM#1 3000.01,2500 r270 bottom
C323 "C-0402_C0402_100NF" DISPLAY_BOTTOM#1 2820.01,2500 r270 bottom
C324 "C-0402_C0402_100NF" DISPLAY_BOTTOM#1 2710,2355.01 r0 bottom
C325 "C-0402_C0402_100NF" DISPLAY_BOTTOM#4 3095,2329.99 r0 bottom
C326 "C-0402_C0402_100NF" DISPLAY_BOTTOM#1 2844.99,2110 r90 bottom
C327 "C-0402_C0402_100NF" DISPLAY_BOTTOM#1 2710,2435.01 r0 bottom
C328 "C-0402_C0402_100NF" DISPLAY_BOTTOM#1 2409.99,2055 r90 bottom
C329 "C-0402_C0402_100NF" DISPLAY_BOTTOM#4 1875,1969.99 r0 bottom
C330 "C-0402_C0402_100NF" DISPLAY_BOTTOM#1 2080,2410.01 r0 bottom
C331 "C-0402_C0402_100NF" DISPLAY_BOTTOM#4 2205,2409.99 r0 bottom
C332 "C-0402_C0402_100NF" DISPLAY_BOTTOM#1 1935,2410.01 r0 bottom
C333 "C-0402_C0402_100NF" DISPLAY_BOTTOM#1 2019.99,2055 r90 bottom
C334 "C-0402_C0402_100NF" DISPLAY_BOTTOM#1 1935,2490.01 r0 bottom
C335 "C-0402_C0402_100NF" DISPLAY_BOTTOM#1 2335.01,2405 r270 bottom
C336 "C-0402_C0402_100NF" DISPLAY_BOTTOM#1 1145,2305.01 r0 bottom
C337 "C-0402_C0402_100NF" DISPLAY_BOTTOM#1 1420.01,2460 r270 bottom
C338 "C-0402_C0402_100NF" DISPLAY_BOTTOM#4 1545,2225 r0 bottom
C339 "C-0402_C0402_100NF" DISPLAY_BOTTOM#1 1145,2265.01 r0 bottom
C340 "C-0402_C0402_100NF" DISPLAY_BOTTOM#1 1349.99,2060 r90 bottom
C341 "C-0402_C0402_100NF" DISPLAY_BOTTOM#1 1270.01,2460 r270 bottom
C342 "C-0402_C0402_100NF" DISPLAY_TOP#3 4459.99,1245 r270 top
C343 "C-0402_C0402_100NF" DISPLAY_TOP#3 4325,1104.99 r0 top
C344 "C-0402_C0402_100NF" DISPLAY_TOP#3 4945.01,1015 r90 top
C345 "C-0402_C0402_NC/100NF" DISPLAY_TOP#3 3536,2579 r270 top
C346 "C-0402_C0402_NC/100NF" DISPLAY_TOP#3 3500.99,2579 r270 top
C347 "C-0402_C0402_100NF" DISPLAY_TOP#3 3625,2605.01 r180 top
C348 "C-0402_C0402_100NF" ASSEMBLY_TOP#3 3810,1170.01 r180 top
C349 "C-0402_C0402_100NF" ASSEMBLY_TOP#3 3715,1260 r0 top
C350 "C-0402_C0402_100NF" DISPLAY_TOP#3 3715,1225 r0 top
C351 "C-0402_C0402_100NF" DISPLAY_TOP#3 3859.99,1840 r270 top
C352 "C-0402_C0402_100NF" DISPLAY_TOP#3 3899.99,1840 r270 top
C353 "C-0402_C0402_NC/100NF" DISPLAY_TOP#3 3440,1650.01 r180 top
C354 "C-0402_C0402_NC/100NF" DISPLAY_TOP#3 3440,1685.01 r180 top
C355 "C-0603_C0603_10UF" ASSEMBLY_TOP#2 4735,1640 r180 top
C356 "C-0603_C0603_10UF" ASSEMBLY_TOP#2 4639,1975 r180 top
C357 "C-0603_C0603_10UF" DISPLAY_BOTTOM#3 1830,2050 r270 bottom
C358 "C-0603_C0603_10UF" DISPLAY_BOTTOM#3 2090,1975 r0 bottom
C359 "C-0603_C0603_10UF" DISPLAY_BOTTOM#3 2385,2425 r270 bottom
C360 "C-0603_C0603_10UF" DISPLAY_BOTTOM#3 1975,1975 r0 bottom
C361 "C-0402_C0402_100NF" DISPLAY_BOTTOM#1 2074.99,2055 r90 bottom
C362 "C-0603_C0603_10UF" DISPLAY_BOTTOM#3 2775,1975 r0 bottom
C363 "C-0603_C0603_10UF" DISPLAY_BOTTOM#2 3150,2410 r0 bottom
C364 "C-0402_C0402_100NF" DISPLAY_BOTTOM#1 2335.01,2325 r270 bottom
C365 "C-0603_C0603_10UF" DISPLAY_TOP#2 4245,1265 r90 top
C366 "C-0603_C0603_10UF" DISPLAY_TOP#2 4410,1265 r270 top
C367 "C-0603_C0603_10UF" DISPLAY_TOP#2 4650,1325 r180 top
C368 "C-0603_C0603_10UF" DISPLAY_TOP#2 4300,1265 r90 top
C369 "C-0402_C0402_NC/11PF" DISPLAY_TOP#3 620,435.01 r180 top
C527 "C-0402_C0402_100NF" ASSEMBLY_TOP#3 4010,560 r180 top
C528 "C-0402_C0402_100NF" ASSEMBLY_TOP#3 4010,518.01 r180 top
C529 "C-0402_C0402_100NF" ASSEMBLY_TOP#3 4011,632.01 r180 top
C530 "C-0402_C0402_100NF" ASSEMBLY_TOP#3 4010,595.01 r180 top
C531 "C-0402_C0402_1UF" ASSEMBLY_BOTTOM#1 5120,475 r90 bottom
C532 "C-0402_C0402_1UF" ASSEMBLY_TOP#3 4930,510 r90 top
C533 "C-0402_C0402_100NF" ASSEMBLY_BOTTOM#1 4985,590 r270 bottom
C806 "C-0805_C0805_22UF" DISPLAY_TOP#4 1240,2005 r0 top
C807 "C-1206_C1206_10UF" DISPLAY_TOP#1 920,2325 r0 top
C808 "C-1206_C1206_10UF" DISPLAY_TOP#1 920,2410 r0 top
C809 "C-0402_C0402_100NF" DISPLAY_TOP#3 1095.01,2210 r90 top
C810 "C-0402_C0402_100NF" DISPLAY_TOP#3 805,2075 r270 top
C811 "C-0805_C0805_22UF" DISPLAY_TOP#4 1240,1930 r0 top
C812 "C-0805_C0805_22UF" DISPLAY_TOP#4 1240,1855 r0 top
C813 "C-0805_C0805_22UF" DISPLAY_TOP#4 935,1740 r90 top
C814 "C-0402_C0402_2.2UF" DISPLAY_TOP#3 865,2260.01 r180 top
C815 "C-0402_C0402_1NF" DISPLAY_TOP#3 790,2135 r0 top
C870 "C-AL-SMD_CAPAE660X770_100UF/35V" ASSEMBLY_TOP#1 1145,1675 r0 top
C871 "C-0402_C0402_100NF" DISPLAY_TOP#3 1210,2060 r0 top
C1010 "C-0603_C0603_10UF" DISPLAY_TOP#2 835,1755 r0 top
C1011 "C-0603_C0603_10UF" DISPLAY_TOP#2 695,1825 r0 top
C1012 "C-0402_C0402_1UF" DISPLAY_TOP#3 925,1645 r0 top
C1013 "C-0603_C0603_10UF" DISPLAY_TOP#2 1165,550 r90 top
C1014 "C-0402_C0402_NC/100NF" DISPLAY_TOP#3 970,559.99 r0 top
C1015 "C-0603_C0603_10UF" DISPLAY_TOP#2 1165,435 r270 top
C1016 "C-0402_C0402_100NF" DISPLAY_TOP#3 1095,405 r0 top
C1017 "C-0603_C0603_10UF" DISPLAY_TOP#2 1455,500 r90 top
C1018 "C-0402_C0402_NC/100NF" DISPLAY_TOP#3 1265,469.99 r0 top
C1019 "C-0603_C0603_10UF" DISPLAY_TOP#2 1455,385 r270 top
C1020 "C-0402_C0402_100NF" DISPLAY_TOP#3 1375,355 r0 top
C1022 "C-0402_C0402_100NF" DISPLAY_TOP#3 1029.99,380 r270 top
C1023 "C-0402_C0402_100NF" DISPLAY_TOP#3 1499.99,370 r270 top
C1024 "C-0402_C0402_100NF" DISPLAY_TOP#3 955,380 r270 top
C1025 "C-0402_C0402_100NF" DISPLAY_TOP#3 1265,335 r180 top
C1026 "C-0402_C0402_100NF" DISPLAY_TOP#3 995,380 r270 top
C1027 "C-0402_C0402_100NF" DISPLAY_TOP#3 1539.99,370 r270 top
C1028 "C-0402_C0402_100NF" DISPLAY_TOP#3 330,674 r180 top
C1029 "C-0402_C0402_100NF" DISPLAY_TOP#3 335,835 r180 top
C1030 "C-0402_C0402_100NF" DISPLAY_TOP#3 335,795 r180 top
C1031 "C-0603_C0603_1UF" DISPLAY_BOTTOM#3 138,2625 r0 bottom
C1032 "C-0603_C0603_10UF" DISPLAY_TOP#2 1090,1215 r0 top
C1033 "C-0603_C0603_10UF" DISPLAY_TOP#2 1170,1010 r180 top
C1034 "C-0402_C0402_1UF" DISPLAY_TOP#3 1285,1310 r180 top
C1035 "C-0402_C0402_100NF" ASSEMBLY_TOP#3 4325.01,2145 r90 top
C1036 "C-0402_C0402_1UF" DISPLAY_TOP#3 4395,635 r180 top
C1037 "C-0603_C0603_10UF" ASSEMBLY_TOP#2 4060,880 r180 top
C1038 "C-0402_C0402_1UF" ASSEMBLY_TOP#3 3969.99,935 r270 top
C1039 "C-0402_C0402_NC/47PF" DISPLAY_TOP#3 4165,909.99 r0 top
C1040 "C-0603_C0603_22UF" ASSEMBLY_TOP#2 3965,1210 r270 top
C1041 "C-0603_C0603_22UF" ASSEMBLY_TOP#2 3910,1095 r90 top
C1042 "C-0603_C0603_22UF" ASSEMBLY_TOP#2 3965,1095 r90 top
C1044 "C-0402_C0402_100NF" ASSEMBLY_TOP#3 3929.99,935 r270 top
C1045 "C-0402_C0402_100NF" DISPLAY_TOP#3 4165,1030.01 r180 top
C1046 "C-0603_C0603_10UF" DISPLAY_TOP#2 3415,285 r270 top
C1047 "C-0603_C0603_10UF" DISPLAY_TOP#2 3550,285 r270 top
C1048 "C-0402_C0402_11PF" DISPLAY_TOP#3 2015,345 r180 top
C1049 "C-0402_C0402_100NF" ASSEMBLY_TOP#3 3440,1410 r0 top
C1050 "C-0402_C0402_100NF" ASSEMBLY_TOP#3 3440,1370 r0 top
D1 "DI-XI-S_SMAF_IC_SM340AF" SILKSCREEN_TOP#1 895,2510 r0 top
D2 "DI-XI-S_SMAF_IC_SM340AF" SILKSCREEN_TOP#1 895,2625 r0 top
D3 "DI-XI-S_SMB_DO-214AA_IC_SMBJ30A" DISPLAY_TOP#5 705,2575 r270 top
D4 "DI-ESD_V0402_PE0402N12G01B" DISPLAY_TOP#6 5065,2535 r90 top
D5 "DI-ESD_V0402_PE0402N12G01B" DISPLAY_TOP#6 5065,2620 r90 top
D6 "DI-ESD_V0402_PE0402N12G01B" DISPLAY_TOP#6 5065,2115 r90 top
D7 "DI-ESD_V0402_PE0402N12G01B" DISPLAY_TOP#6 5065,2200 r90 top
D8 "DI-ESD_V0402_PE0402N12G01B" DISPLAY_TOP#6 3475,2845 r180 top
D9 "DI-ESD_V0402_PE0402N12G01B" DISPLAY_TOP#6 3390,2845 r180 top
D18 "DI-XI-S_SMAF_IC_SM340AF" SILKSCREEN_BOTTOM#1 140,2225 r90 bottom
D20 "DI-ESD-SE05NRC14GA_DFN2510-10L_" DISPLAY_TOP#7 655,2075 r90 top
D21 "DI-ESD-SE05NRC14GA_DFN2510-10L_" DISPLAY_TOP#7 655,2235 r90 top
D24 "DI-ESD-SE05NRC14GA_DFN2510-10L_" DISPLAY_TOP#7 655,2345 r270 top
D33 "DI-TVS-SRV05-4_SOT23-6_SRV05-4" SILKSCREEN_BOTTOM#2 3000,2625 r90 bottom
D34 "DI-TVS-SRV05-4_SOT23-6_SRV05-4" SILKSCREEN_BOTTOM#2 2820,2625 r90 bottom
D35 "DI-ESD-SRV05-4_SOT23-6_SRV05-4" SILKSCREEN_BOTTOM#2 2225,2620 r270 bottom
D36 "DI-ESD-SRV05-4_SOT23-6_SRV05-4" SILKSCREEN_BOTTOM#2 2065,2620 r270 bottom
D37 "DI-ESD_V0402_PE0402N12G01B" DISPLAY_TOP#6 2975,3125 r90 top
D38 "DI-ESD_V0402_PE0402N12G01B" DISPLAY_TOP#6 3030,3125 r90 top
D39 "DI-ESD_V0402_PE0402N12G01B" DISPLAY_TOP#6 3645,2845 r180 top
D40 "DI-ESD_V0402_PE0402N12G01B" DISPLAY_TOP#6 3560,2845 r0 top
D41 "DI-ESD_V0402_PE0402N12G01B" DISPLAY_TOP#6 3305,2845 r180 top
D42 "DI-ESD_V0402_PE0402N12G01B" DISPLAY_TOP#6 3220,2845 r0 top
D43 "DI-XI-S_SOD523_IC_LRB520S-30T1G" DISPLAY_TOP#8 4980,1555 r180 top
D46 "DI-ESD_V0402_PE0402N12G01B" DISPLAY_TOP#6 3010,3250 r270 top
D48 "DI-XI-S_SOD523_IC_LRB520S-30T1G" DISPLAY_TOP#8 2685,525 r0 top
D49 "DI-XI-S_SOD523_IC_LRB520S-30T1G" DISPLAY_TOP#8 2565,525 r180 top
D50 "DI-ESD_V0402_PE0402N12G01B" DISPLAY_TOP#6 5020,1380 r270 top
D51 "DI-ESD_V0402_PE0402N12G01B" DISPLAY_BOTTOM#5 5205,3255 r270 bottom
D65 "DI-ESD_V0402_PE0402N12G01B" DISPLAY_BOTTOM#5 5115,3255 r90 bottom
D66 "DI-ESD_V0402_PE0402N12G01B" DISPLAY_TOP#6 4785,2935 r0 top
D67 "DI-ESD_V0402_PE0402N12G01B" DISPLAY_TOP#6 4870,2935 r0 top
D68 "DI-ESD_V0402_PE0402N12G01B" DISPLAY_TOP#6 4615,2935 r0 top
D69 "DI-ESD_V0402_PE0402N12G01B" DISPLAY_TOP#6 4530,2865 r0 top
D79 "DI-TVS-D_SOD-123F_SMF6.0CA" SILKSCREEN_TOP#2 3430,795 r90 top
D80 "DI-TVS-SRV05-4_SOT23-6_SRV05-4" SILKSCREEN_BOTTOM#2 1345,2590 r270 bottom
D194 "DI-TVS-D_SOD-123F_NC/SMF16CA" SILKSCREEN_BOTTOM#3 4930,740 r90 bottom
D195 "DI-TVS-D_SOD-123F_NC/SMF16CA" SILKSCREEN_BOTTOM#3 4930,570 r270 bottom
F3 "FUSE-RL30-300-SIP2_SIP2-10D-510" ASSEMBLY_TOP#5 500,2855 r270 top
F4 "FUSE-SMD1812_SMD1812_NC/FUSE_33" ASSEMBLY_TOP#6 500,2855 r270 top
HOLE5 "MH-NOE_MTG370_600_VIA_MTG370_60" ASSEMBLY_TOP#7 205,205 r0 top
HOLE9 "MH-NOE_MTG370_600_VIA_MTG370_60" ASSEMBLY_TOP#7 5120,2950 r0 top
HOLE10 "MH-NOE_MTG370_600_VIA_MTG370_60" ASSEMBLY_TOP#7 5120,205 r0 top
HOLE11 "MH-NOE_MTG370_600_VIA_MTG370_60" ASSEMBLY_TOP#7 205,2950 r0 top
J1 "J-DC-044A-2_5_DC-044A-2_0-DIP_D" SILKSCREEN_TOP#3 311.2,3381.65 r270 top
J2 "J-H-3P_PBZ_ICSRC6508SFR_J-H-3P" DISPLAY_TOP#9 1820.5,580.38 r0 top
J3 "J-H-3P_PBZ_ICSRC6508SFR_J-H-3P" DISPLAY_TOP#9 1354.62,2135.5 r90 top
J4 "J-H-3P_PBZ_ICSRC6508SFR_J-H-3P" DISPLAY_TOP#9 3364.62,1045.5 r90 top
J5 "J-H-3P_PBZ_ICSRC6508SFR_J-H-3P" DISPLAY_TOP#9 1820.5,2595.38 r0 top
J6 "J-TF-01A_TF-01A_SD" SILKSCREEN_TOP#4 4184.96,3237.95 r180 top
J7 "J-H-4P_PH200-4A_PH2.0-4A" ASSEMBLY_TOP#8 5222.72,2540 r270 top
J8 "J-H-4P_PH200-4A_PH2.0-4A" ASSEMBLY_TOP#8 5222.72,2090 r270 top
J10 "J-MINIPCIE-52P_0_M_MINIPCIE_SOC" SILKSCREEN_TOP#5 4312,2431.95 r0 top
J11 "J-SIM-021_SIM-91288-021_SIM" SILKSCREEN_BOTTOM#4 4323.43,2948.46 r270 bottom
J13 "J-FPC-6P_FPC05-6P_FPC05-UD-6P" ASSEMBLY_TOP#9 146.85,1750 r270 top
J15 "J-HDR-5_HDR200MA-1X5_HDR200MA-1" ASSEMBLY_TOP#10 270,1257.48 r90 top
J16 "J-HDR-D-20_HDR200MA-2X10_HDR200" ASSEMBLY_TOP#11 500.63,2169.33 r90 top
J18 "J-FPC-30P_FPC05-30P_FPC05-FDW-3" ASSEMBLY_TOP#12 1695,151.85 r0 top
J19 "J-FPC-24P_FPC05-24P_FPC05-PUW-2" ASSEMBLY_TOP#13 750,151.85 r0 top
J20 "J-FPC-30P_1_B2B_30P-40-S_B2B_30" SILKSCREEN_TOP#6 142.59,705 r90 top
J21 "J-RJ45-HY911130A_RJ45-TH_HY9111" ASSEMBLY_TOP#14 2485,3199.84 r0 top
J22 "J-RJ45-HY911130A_RJ45-TH_HY9111" ASSEMBLY_TOP#14 1715,3199.84 r0 top
J23 "J-RJ45-HR911105A_0_RJ45-TH_HR91" SILKSCREEN_TOP#7 955,3193.94 r180 top
J24 "RF-PIEX-1_IPEX-001E_IPEX_1" ASSEMBLY_TOP#15 5191.63,783.27 r180 top
J27 "J-M2_NGFF-M-KEY_1_M2_NGFF-M-KEY" SILKSCREEN_BOTTOM#5 2385,1465 r0 bottom
J28 "J-A-3P_MX125T-S-3AW_MX1.25T-S-3" SILKSCREEN_TOP#8 5185.55,1640 r90 top
J35 "J-H-4P_PH200-4A_PH2.0-4A" ASSEMBLY_TOP#16 2865,100 r180 top
J36 "J-A-2P_MX125T-S-2A_MX1.25T-S-2A" SILKSCREEN_TOP#9 5130,3255.87 r180 top
J37 "J-PJ-316A-6A_PJ-316A-6A_PJ-316-" ASSEMBLY_TOP#17 4763.03,3341.34 r90 top
J42 "J-USB-9AFX2-DIP-W_USB-9AF-DIP_2" SILKSCREEN_TOP#10 3430,3269.33 r180 top
J43 "J-H-6P_PH200-6A_PH2.0-6A" ASSEMBLY_TOP#18 92.28,1275 r90 top
J44 "J-HDR-D-20_HDR254MA-2X10_HDR254" ASSEMBLY_TOP#19 4388.62,130.59 r180 top
J45 "J-FPC-6P_FPC10-6P_FPC10-FDW-6P" SILKSCREEN_TOP#11 2375,160 r0 top
J46 "J-FPC-24P_FPC05-24P_FPC05-PUW-2" ASSEMBLY_TOP#13 146.85,2400 r270 top
J47 "RTC-VBAT-2P_CR1220-2P-SMD_CR122" ASSEMBLY_TOP#20 691.5,952.75 r0 top
J48 "J-H-3P_PBZ_ICSRC6508SFR_J-H-3P" DISPLAY_TOP#9 2910.5,2595.38 r0 top
J49 "J-H-3P_PBZ_ICSRC6508SFR_J-H-3P" DISPLAY_TOP#9 2910.5,580.38 r0 top
J50 "J-H-3P_PBZ_ICSRC6508SFR_J-H-3P" DISPLAY_TOP#9 1354.62,1045.5 r90 top
J51 "J-H-3P_PBZ_ICSRC6508SFR_J-H-3P" DISPLAY_TOP#9 3364.62,2135.5 r90 top
J54 "J-H-4P_PH200-4A_PH2.0-4A" ASSEMBLY_TOP#8 3270,100 r180 top
J55 "J-H-4P_PH200-4A_PH2.0-4A" ASSEMBLY_TOP#8 3675,100 r180 top
J56 "J-H-4P_PH200-4A_PH2.0-4A" ASSEMBLY_TOP#8 5225,1175 r270 top
L3 "L-IND_IND_252012_1UH/3A" ASSEMBLY_TOP#21 1190,1485 r0 top
L7 "L-IND_IND_252012_1UH/3A" ASSEMBLY_TOP#21 3655,2195 r0 top
L8 "L-IND_IND_252012_4.7UH/1.25A" ASSEMBLY_BOTTOM#2 135,2055 r90 bottom
L11 "FB-0603_L0603_UPZ1608E101-3R0TF" DISPLAY_BOTTOM#6 1550,2445 r0 bottom
L12 "FB-0603_L0603_UPZ1608E101-3R0TF" DISPLAY_BOTTOM#7 1550,2500 r0 bottom
L13 "L-IND_IND_252012_4.7UH/1.25A" ASSEMBLY_TOP#21 4530,1269.5 r90 top
L25 "FB-0603_L0603_UPZ1608E101-3R0TF" DISPLAY_TOP#10 3165,335 r270 top
L26 "FB-0603_L0603_UPZ1608E101-3R0TF" DISPLAY_TOP#10 3255,315 r180 top
L27 "FB-0603_L0603_UPZ1608E101-3R0TF" DISPLAY_TOP#10 3095,335 r270 top
L28 "FB-0603_L0603_UPZ1608E101-3R0TF" DISPLAY_TOP#10 3020,335 r270 top
L29 "FB-0603_L0603_UPZ1608E101-3R0TF" DISPLAY_TOP#10 3825,1125 r180 top
L31 "L-IND_IND_252012_4.7UH/1.25A" ASSEMBLY_BOTTOM#3 1935,2045 r0 bottom
L32 "L-IND_IND_252012_4.7UH/1.25A" ASSEMBLY_BOTTOM#4 2775,2074.5 r270 bottom
L33 "L-IND_IND_73X66_2.2UH/9.5A" ASSEMBLY_TOP#22 995,1955 r0 top
L40 "FB-0402_L0402_GZ1005D121TF" DISPLAY_TOP#11 4010,483 r180 top
L41 "FB-0402_L0402_GZ1005D121TF" DISPLAY_TOP#11 3945,450 r180 top
L42 "FB-0402_L0402_GZ1005D121TF" DISPLAY_TOP#11 4395,545 r0 top
L43 "FB-0402_L0402_GZ1005D121TF" DISPLAY_TOP#11 4395,580 r0 top
L44 "L-IND_IND_252012_1UH/3A" ASSEMBLY_TOP#21 4045,1134.5 r90 top
L45 "FB-0402_L0402_GZ1005D121TF" ASSEMBLY_BOTTOM#5 5110,590 r90 bottom
L46 "FB-0402_L0402_GZ1005D121TF" ASSEMBLY_BOTTOM#5 5075,590 r90 bottom
LED1 "D-LED-CT_LED-SMD_3_2X1_5X1_0_YE" ASSEMBLY_TOP#23 2975,3489.84 r180 top
LED2 "D-LED0603_LED0603_BLUE LED0603" SILKSCREEN_TOP#12 3625,2390 r0 top
M1 "SOM3562_3_SOM3562-182P_SOM3562" SILKSCREEN_TOP#13 2360.83,1585.83 r0 top
M6 "MH-NOE_MTG380_620_SMTSO_M2_SMTS" ASSEMBLY_TOP#24 4785,540 r0 top
Q1 "N-MOS-Q_SOT523_MMFTN3019E" DISPLAY_TOP#12 2925,3360 r90 top
Q3 "P-MOS_SOT23_CJ3401" DISPLAY_TOP#13 475,1655 r90 top
Q4 "N-MOS-Q_SOT523_MMFTN3019E" DISPLAY_TOP#12 370,1635 r270 top
Q5 "N-MOS-Q_SOT523_MMFTN3019E" DISPLAY_TOP#12 4060,730 r180 top
Q6 "N-MOS-Q_SOT523_MMFTN3019E" DISPLAY_TOP#12 3625,2490 r270 top
Q7 "N-MOS-Q_SOT523_MMFTN3019E" DISPLAY_TOP#12 695,1700 r270 top
Q8 "P-MOS_SOT23_CJ3401" DISPLAY_TOP#13 810,1665 r180 top
Q9 "N-MOS-Q_SOT523_MMFTN3019E" DISPLAY_TOP#12 1250,1125 r90 top
Q10 "P-MOS_SOT23_CJ3401" DISPLAY_TOP#13 1150,1110 r270 top
R4 "R-0402_R0402_100K" DISPLAY_TOP#3 695,1775 r0 top
R8 "R-0402_R0402_45.3K" DISPLAY_TOP#3 965,1315 r270 top
R9 "R-0402_R0402_1K" DISPLAY_TOP#3 1085,1315 r90 top
R10 "R-0402_R0402_10K" DISPLAY_TOP#3 1005,1315 r90 top
R11 "R-0402_R0402_2.2K" DISPLAY_TOP#3 2815,425 r180 top
R12 "R-0402_R0402_2.2K" DISPLAY_TOP#3 2815,480 r180 top
R13 "R-0402_R0402_2.2K" DISPLAY_TOP#3 1550,455 r270 top
R14 "R-0402_R0402_2.2K" DISPLAY_TOP#3 1510,455 r270 top
R15 "R-0402_R0402_2.2K" DISPLAY_TOP#3 905,460 r270 top
R16 "R-0402_R0402_2.2K" DISPLAY_TOP#3 865,460 r270 top
R17 "R-0402_R0402_100K" DISPLAY_TOP#3 3436,993 r0 top
R19 "R-0402_R0402_1K" DISPLAY_TOP#3 3065,3360 r90 top
R21 "R-0402_R0402_1K" DISPLAY_TOP#3 2985,3360 r90 top
R25 "R-0402_R0402_22R" DISPLAY_TOP#3 3060,2675 r90 top
R28 "R-0402_R0402_100R" ASSEMBLY_TOP#3 4440,2850 r90 top
R29 "R-0402_R0402_2.2R" ASSEMBLY_TOP#3 5000,2560 r0 top
R30 "R-0402_R0402_2.2R" ASSEMBLY_TOP#3 5000,2595 r0 top
R31 "R-0402_R0402_4.7K" DISPLAY_TOP#3 4950,2475 r0 top
R32 "R-0402_R0402_2.2R" ASSEMBLY_TOP#3 5000,2140 r0 top
R33 "R-0402_R0402_2.2R" ASSEMBLY_TOP#3 5000,2175 r0 top
R34 "R-0402_R0402_4.7K" DISPLAY_TOP#3 4950,2055 r0 top
R35 "R-0402_R0402_4.7K" ASSEMBLY_TOP#3 3970,2775 r270 top
R36 "R-0402_R0402_0R" ASSEMBLY_TOP#3 4090,1679 r0 top
R37 "R-0402_R0402_2.2R" DISPLAY_TOP#3 3450,2780 r90 top
R38 "R-0402_R0402_2.2R" DISPLAY_TOP#3 3415,2780 r90 top
R43 "R-0402_R0402_1M" ASSEMBLY_TOP#3 4685,1895 r90 top
R45 "R-0402_R0402_NC/100K" ASSEMBLY_TOP#3 4090,1639 r180 top
R47 "R-0402_R0402_2.7K" ASSEMBLY_TOP#3 4180,1820 r180 top
R48 "R-0402_R0402_0R" ASSEMBLY_TOP#3 4090,1599 r0 top
R49 "R-0402_R0402_0R" ASSEMBLY_TOP#3 4100,2145 r90 top
R50 "R-0402_R0402_0R" ASSEMBLY_TOP#3 4065,2145 r90 top
R52 "R-0402_R0402_0R" ASSEMBLY_TOP#3 4700,2165 r0 top
R53 "R-0402_R0402_15K" ASSEMBLY_TOP#3 4700,2125 r0 top
R54 "R-0402_R0402_22R" ASSEMBLY_TOP#3 4640,2145 r270 top
R55 "R-0402_R0402_22R" ASSEMBLY_TOP#3 4600,2145 r270 top
R56 "R-0402_R0402_22R" ASSEMBLY_TOP#3 4560,2145 r270 top
R60 "R-0402_R0402_53.6K" DISPLAY_TOP#3 3600,1960 r270 top
R62 "R-0402_R0402_0R" DISPLAY_BOTTOM#1 265,1770 r90 bottom
R75 "R-0402_R0402_22R" DISPLAY_BOTTOM#1 290,1910 r90 bottom
R78 "R-0402_R0402_1K" DISPLAY_TOP#3 1610,2670 r270 top
R80 "R-0402_R0402_100K" DISPLAY_TOP#3 400,1540 r270 top
R82 "R-0402_R0402_100K" DISPLAY_BOTTOM#1 270,1970 r0 bottom
R84 "R-0402_R0402_100K" DISPLAY_BOTTOM#1 285,2200 r90 bottom
R98 "R-0402_R0402_22R" DISPLAY_TOP#3 285,1550 r180 top
R99 "R-0402_R0402_22R" DISPLAY_TOP#3 285,1600 r180 top
R113 "R-0402_R0402_NC/10K" DISPLAY_TOP#3 1660,370 r270 top
R123 "R-0402_R0402_22R" DISPLAY_TOP#3 1305,1580 r270 top
R124 "R-0402_R0402_22R" DISPLAY_TOP#3 1700,370 r270 top
R125 "R-0402_R0402_22R" DISPLAY_TOP#3 1590,455 r270 top
R126 "R-0402_R0402_22R" DISPLAY_TOP#3 1620,370 r270 top
R127 "R-0402_R0402_22R" DISPLAY_TOP#3 1580,370 r270 top
R128 "R-0402_R0402_22R" DISPLAY_TOP#3 905,380 r270 top
R129 "R-0402_R0402_22R" DISPLAY_TOP#3 865,380 r270 top
R130 "R-0402_R0402_4.7K" DISPLAY_TOP#3 440,585 r180 top
R132 "R-0402_R0402_49.9K" DISPLAY_TOP#3 375,385 r0 top
R133 "R-0402_R0402_20K" DISPLAY_TOP#3 350,445 r270 top
R134 "R-0402_R0402_24.9K" DISPLAY_TOP#3 1095,705 r180 top
R135 "R-0402_R0402_20K" DISPLAY_TOP#3 1095,745 r0 top
R136 "R-0402_R0402_10K" DISPLAY_TOP#3 2015,380 r180 top
R137 "R-0402_R0402_20K" DISPLAY_TOP#3 2015,415 r0 top
R138 "R-0402_R0402_17.4K" DISPLAY_TOP#3 620,470 r180 top
R139 "R-0402_R0402_20K" DISPLAY_TOP#3 620,505 r0 top
R140 "R-0402_R0402_2.2R" DISPLAY_BOTTOM#1 3070,2500 r90 bottom
R141 "R-0402_R0402_2.2R" DISPLAY_BOTTOM#1 2965,2500 r90 bottom
R142 "R-0402_R0402_2.2R" DISPLAY_BOTTOM#1 2930,2500 r90 bottom
R144 "R-0402_R0402_2.2R" DISPLAY_BOTTOM#1 2785,2500 r90 bottom
R145 "R-0402_R0402_2.2R" DISPLAY_BOTTOM#1 2750,2500 r90 bottom
R147 "R-0402_R0402_2.2R" DISPLAY_BOTTOM#1 3035,2500 r90 bottom
R148 "R-0402_R0402_2.2R" DISPLAY_BOTTOM#1 2890,2500 r90 bottom
R149 "R-0402_R0402_2.2R" DISPLAY_BOTTOM#1 2855,2500 r90 bottom
R150 "R-0402_R0402_510R" DISPLAY_TOP#3 2885,2880 r0 top
R153 "R-0402_R0402_0R" DISPLAY_BOTTOM#1 2995,2010 r90 bottom
R154 "R-0402_R0402_0R" DISPLAY_BOTTOM#1 2955,2010 r90 bottom
R155 "R-0402_R0402_0R" DISPLAY_BOTTOM#1 3185,2330 r270 bottom
R156 "R-0402_R0402_0R" DISPLAY_BOTTOM#1 2995,2110 r90 bottom
R157 "R-0402_R0402_510R" DISPLAY_TOP#3 2185,2670 r270 top
R158 "R-0402_R0402_2.49K" DISPLAY_BOTTOM#1 2710,2395 r0 bottom
R159 "R-0402_R0402_0R" DISPLAY_BOTTOM#1 2880,2030 r90 bottom
R160 "R-0402_R0402_0R" DISPLAY_BOTTOM#4 3135,2460 r0 bottom
R161 "R-0402_R0402_NC/1K" DISPLAY_BOTTOM#1 2955,2110 r90 bottom
R162 "R-0402_R0402_2.2R" DISPLAY_BOTTOM#1 2285,2490 r90 bottom
R163 "R-0402_R0402_2.2R" DISPLAY_BOTTOM#1 2250,2490 r90 bottom
R164 "R-0402_R0402_2.2R" DISPLAY_BOTTOM#1 2195,2490 r90 bottom
R165 "R-0402_R0402_2.2R" DISPLAY_BOTTOM#1 2160,2490 r90 bottom
R166 "R-0402_R0402_2.2R" DISPLAY_BOTTOM#1 2120,2490 r90 bottom
R167 "R-0402_R0402_2.2R" DISPLAY_BOTTOM#1 2085,2490 r90 bottom
R168 "R-0402_R0402_2.2R" DISPLAY_BOTTOM#1 2040,2490 r90 bottom
R169 "R-0402_R0402_2.2R" DISPLAY_BOTTOM#1 2005,2490 r90 bottom
R170 "R-0402_R0402_100R" DISPLAY_BOTTOM#1 1935,2180 r0 bottom
R171 "R-0402_R0402_120R" DISPLAY_BOTTOM#4 1820,2170 r0 bottom
R172 "R-0402_R0402_22R" DISPLAY_BOTTOM#1 2415,2325 r270 bottom
R174 "R-0402_R0402_4.7K" DISPLAY_BOTTOM#1 1935,2140 r0 bottom
R175 "R-0402_R0402_4.7K" DISPLAY_TOP#3 2075,2670 r270 top
R176 "R-0402_R0402_4.7K" DISPLAY_TOP#3 1465,2670 r90 top
R177 "R-0402_R0402_22R" DISPLAY_BOTTOM#1 1590,2010 r0 bottom
R178 "R-0402_R0402_4.7K" DISPLAY_BOTTOM#1 2370,2055 r270 bottom
R179 "R-0402_R0402_4.7K" DISPLAY_BOTTOM#1 2130,2055 r90 bottom
R180 "R-0402_R0402_4.7K" DISPLAY_BOTTOM#1 2205,2055 r90 bottom
R181 "R-0402_R0402_4.7K" DISPLAY_BOTTOM#1 2245,2055 r90 bottom
R182 "R-0402_R0402_NC/4.7K" DISPLAY_BOTTOM#1 2280,2055 r270 bottom
R183 "R-0402_R0402_2.49K" DISPLAY_BOTTOM#1 1935,2450 r0 bottom
R184 "R-0402_R0402_4.7K" DISPLAY_BOTTOM#1 2320,2055 r90 bottom
R185 "R-0402_R0402_NC/4.7K" DISPLAY_BOTTOM#4 2315,1965 r0 bottom
R187 "R-0402_R0402_NC/4.7K" DISPLAY_BOTTOM#1 1590,1970 r0 bottom
R188 "R-0402_R0402_4.7K" DISPLAY_BOTTOM#1 1670,1970 r0 bottom
R189 "R-0402_R0402_510R" DISPLAY_TOP#3 2115,2670 r270 top
R190 "R-0402_R0402_100K" DISPLAY_BOTTOM#1 2375,2325 r90 bottom
R191 "R-0402_R0402_1.8K" DISPLAY_BOTTOM#1 2355,2265 r0 bottom
R192 "R-0402_R0402_22R" DISPLAY_BOTTOM#1 2170,2055 r270 bottom
R193 "R-0402_R0402_510R" DISPLAY_TOP#3 1505,2670 r270 top
R194 "R-0402_R0402_0R" DISPLAY_BOTTOM#1 2435,2405 r270 bottom
R195 "R-0402_R0402_4.7K" DISPLAY_BOTTOM#1 1545,2305 r0 bottom
R196 "R-0402_R0402_22R" DISPLAY_BOTTOM#1 1635,2350 r0 bottom
R197 "R-0402_R0402_22R" DISPLAY_BOTTOM#1 1635,2395 r0 bottom
R198 "R-0402_R0402_22R" DISPLAY_BOTTOM#4 3150,2075 r0 bottom
R199 "R-0402_R0402_22R" DISPLAY_BOTTOM#4 3150,2115 r0 bottom
R200 "R-0402_R0402_4.7K" DISPLAY_TOP#3 1330,2875 r180 top
R201 "R-0402_R0402_22R" DISPLAY_BOTTOM#4 3150,2035 r0 bottom
R202 "R-0402_R0402_22R" DISPLAY_BOTTOM#1 3145,1980 r0 bottom
R203 "R-0402_R0402_22R" DISPLAY_BOTTOM#1 3240,2125 r270 bottom
R204 "R-0402_R0402_NC/4.7K" DISPLAY_BOTTOM#1 1390,2060 r270 bottom
R205 "R-0402_R0402_4.7K" DISPLAY_BOTTOM#1 1245,2060 r90 bottom
R206 "RN_0402X4_RN_0402X4_22R" DISPLAY_BOTTOM#8 1345,2460 r90 bottom
R207 "R-0402_R0402_4.7K" DISPLAY_BOTTOM#1 1285,2060 r90 bottom
R208 "R-0402_R0402_22R" DISPLAY_BOTTOM#1 1430,2060 r90 bottom
R209 "R-0402_R0402_2.49K" DISPLAY_BOTTOM#1 1230,2460 r90 bottom
R210 "R-0402_R0402_22R" DISPLAY_BOTTOM#1 1145,2185 r0 bottom
R211 "R-0402_R0402_4.7K" DISPLAY_BOTTOM#1 1635,2305 r0 bottom
R212 "R-0402_R0402_NC/4.7K" DISPLAY_BOTTOM#1 1545,2350 r0 bottom
R213 "R-0402_R0402_22R" DISPLAY_BOTTOM#4 1545,2170 r0 bottom
R215 "R-0402_R0402_22R" DISPLAY_BOTTOM#1 1145,2145 r0 bottom
R216 "R-0402_R0402_4.7K" DISPLAY_BOTTOM#1 1545,2265 r0 bottom
R217 "R-0402_R0402_4.7K" DISPLAY_BOTTOM#1 1540,2395 r0 bottom
R218 "R-0402_R0402_510R" DISPLAY_TOP#3 1330,2955 r180 top
R219 "R-0402_R0402_510R" DISPLAY_TOP#3 1330,2795 r180 top
R220 "R-0402_R0402_4.7K" DISPLAY_BOTTOM#4 1145,2225 r0 bottom
R225 "R-0402_R0402_0R" DISPLAY_TOP#3 5005,783.27 r0 top
R227 "R-0402_R0402_22R" DISPLAY_TOP#3 4685,1245 r270 top
R229 "R-0402_R0402_22R" DISPLAY_TOP#3 4860,1245 r90 top
R235 "R-0402_R0402_22R" DISPLAY_TOP#3 4470,605 r270 top
R237 "R-0402_R0402_NC/22R" DISPLAY_TOP#3 4965,925 r180 top
R238 "R-0402_R0402_0R" DISPLAY_TOP#3 4820,1245 r270 top
R239 "R-0402_R0402_NC/10K" DISPLAY_BOTTOM#1 4560,685 r0 bottom
R240 "R-0603_R0603_0R" DISPLAY_TOP#14 4355,1265 r270 top
R241 "R-0603_R0603_0R" DISPLAY_TOP#14 5025,975 r180 top
R243 "R-0402_R0402_0R" DISPLAY_TOP#3 4325,1025 r0 top
R244 "R-0402_R0402_0R" DISPLAY_TOP#3 4325,890 r0 top
R245 "R-0402_R0402_0R" DISPLAY_TOP#3 4510,605 r90 top
R246 "R-0402_R0402_NC/0R" DISPLAY_TOP#3 4550,605 r90 top
R247 "R-0402_R0402_2.2R" DISPLAY_TOP#3 2985,3040 r90 top
R248 "R-0402_R0402_2.2R" DISPLAY_TOP#3 3020,3040 r90 top
R253 "R-0402_R0402_15K" DISPLAY_TOP#3 3625,2645 r180 top
R258 "R-0402_R0402_NC/0R" DISPLAY_TOP#3 3730,1575 r0 top
R259 "R-0402_R0402_NC/0R" DISPLAY_TOP#3 3730,1615 r0 top
R260 "R-0402_R0402_NC/0R" DISPLAY_TOP#3 3730,1535 r0 top
R261 "R-0402_R0402_4.7K" ASSEMBLY_TOP#3 4980,1645 r180 top
R264 "R-0402_R0402_100R" DISPLAY_TOP#3 2965,3250 r90 top
R266 "R-0402_R0402_100R" DISPLAY_TOP#3 4975,1380 r90 top
R267 "R-0402_R0402_100R" ASSEMBLY_BOTTOM#1 5160,3255 r90 bottom
R299 "R-0603_R0603_0R" ASSEMBLY_TOP#25 3980,730 r270 top
R300 "R-0603_R0603_0R" DISPLAY_TOP#14 3325,495 r180 top
R303 "R-0402_R0402_20K" DISPLAY_TOP#3 3745,890 r0 top
R306 "R-0402_R0402_0R" DISPLAY_TOP#3 3665,945 r0 top
R308 "R-0402_R0402_NC/0R" DISPLAY_TOP#3 3655,1560 r180 top
R309 "R-0402_R0402_20K" DISPLAY_TOP#3 3745,1000 r0 top
R310 "R-0402_R0402_NC/0R" DISPLAY_TOP#3 3655,1615 r180 top
R311 "R-0402_R0402_NC/0R" DISPLAY_TOP#3 3655,1520 r180 top
R314 "R-0402_R0402_100K" ASSEMBLY_TOP#3 4870,2850 r0 top
R316 "R-0402_R0402_0R" ASSEMBLY_TOP#3 4700,2935 r180 top
R318 "R-0603_R0603_0R" DISPLAY_TOP#14 2870,310 r180 top
R341 "R-0402_R0402_4.7K" DISPLAY_TOP#3 3705,2725 r90 top
R342 "R-0402_R0402_NC/0R" DISPLAY_TOP#3 3730,1655 r0 top
R343 "R-0402_R0402_22R" DISPLAY_TOP#3 2690,425 r180 top
R344 "R-0402_R0402_22R" DISPLAY_TOP#3 2690,390 r180 top
R345 "R-0402_R0402_100R" ASSEMBLY_TOP#3 3930,293 r270 top
R346 "R-0402_R0402_100R" ASSEMBLY_TOP#3 3970,293 r270 top
R347 "R-0402_R0402_100R" ASSEMBLY_TOP#3 4010,293 r270 top
R348 "R-0402_R0402_100R" DISPLAY_TOP#3 4050,293 r270 top
R349 "R-0402_R0402_100R" DISPLAY_TOP#3 4370,320 r270 top
R350 "R-0402_R0402_100R" DISPLAY_TOP#3 4410,320 r270 top
R352 "R-0402_R0402_0R" ASSEMBLY_TOP#3 3925,2695 r180 top
R353 "R-0402_R0402_0R" DISPLAY_TOP#3 3625,2725 r180 top
R363 "RN_0402X4_RN_0402X4_22R" DISPLAY_TOP#15 4595,320 r270 top
R365 "RN_0402X4_RN_0402X4_22R" DISPLAY_TOP#15 4275,335 r270 top
R366 "R-0402_R0402_0R" DISPLAY_TOP#3 4795,320 r270 top
R368 "R-0402_R0402_22R" DISPLAY_TOP#3 4715,320 r270 top
R369 "R-0402_R0402_22R" DISPLAY_TOP#3 4675,320 r270 top
R370 "R-0402_R0402_22R" DISPLAY_TOP#3 4510,320 r270 top
R371 "R-0402_R0402_22R" DISPLAY_TOP#3 4470,320 r270 top
R372 "R-0402_R0402_22R" DISPLAY_TOP#3 426,736 r180 top
R373 "R-0402_R0402_4.7K" DISPLAY_TOP#3 1095,825 r0 top
R374 "R-0402_R0402_4.7K" DISPLAY_TOP#3 2100,520 r180 top
R375 "R-0402_R0402_4.7K" DISPLAY_TOP#3 665,595 r180 top
R382 "R-0402_R0402_0R" DISPLAY_TOP#3 1270,975 r0 top
R383 "R-0402_R0402_0R" DISPLAY_TOP#3 1915,2670 r270 top
R384 "R-0402_R0402_0R" DISPLAY_TOP#3 3420,1960 r270 top
R387 "R-0402_R0402_2.2K" ASSEMBLY_TOP#3 4530,2820 r180 top
R388 "R-0402_R0402_2.2K" ASSEMBLY_BOTTOM#1 5070,3255 r270 bottom
R389 "R-0402_R0402_47K" DISPLAY_TOP#3 3436,1073 r180 top
R391 "R-0402_R0402_10K" DISPLAY_TOP#3 4325,985 r0 top
R401 "R-0402_R0402_0R" DISPLAY_BOTTOM#1 3446,2579 r90 bottom
R402 "R-0402_R0402_0R" DISPLAY_BOTTOM#1 3411,2579 r90 bottom
R403 "R-0402_R0402_0R" DISPLAY_TOP#3 3525,1955 r90 top
R404 "R-0402_R0402_0R" DISPLAY_TOP#3 3480,1955 r90 top
R405 "R-0402_R0402_NC/0R" DISPLAY_TOP#3 3440,1720 r0 top
R406 "R-0402_R0402_NC/0R" DISPLAY_TOP#3 3440,1755 r0 top
R407 "R-0402_R0402_NC/0R" DISPLAY_TOP#3 3525,1920 r270 top
R408 "R-0402_R0402_NC/0R" DISPLAY_TOP#3 3480,1920 r270 top
R409 "R-0402_R0402_NC/0R" DISPLAY_TOP#3 3446,2579 r90 top
R410 "R-0402_R0402_NC/0R" DISPLAY_TOP#3 3411,2579 r90 top
R412 "R-0603_R0603_4.99R" DISPLAY_BOTTOM#9 138,2570 r0 bottom
R413 "R-0603_R0603_4.99R" DISPLAY_BOTTOM#9 245,2605 r270 bottom
R414 "R-0402_R0402_0R" ASSEMBLY_TOP#3 4450,1465 r270 top
R415 "R-0402_R0402_10K" DISPLAY_TOP#3 3025,3360 r270 top
R416 "R-0402_R0402_0R" DISPLAY_TOP#3 335,755 r0 top
R417 "R-0402_R0402_NC/10K" DISPLAY_TOP#3 425,700 r0 top
R421 "R-0402_R0402_2.2K" DISPLAY_TOP#3 425,1285 r180 top
R422 "R-0402_R0402_2.2K" DISPLAY_TOP#3 425,1245 r180 top
R423 "R-0402_R0402_NC/0R" DISPLAY_TOP#3 610,1365 r180 top
R425 "R-0402_R0402_NC/2.2K" DISPLAY_TOP#3 4255,275 r0 top
R426 "R-0402_R0402_NC/2.2K" DISPLAY_TOP#3 4165,275 r0 top
R429 "R-0402_R0402_0R" DISPLAY_TOP#3 3625,2305 r180 top
R430 "R-0402_R0402_NC/0R" DISPLAY_TOP#3 3625,2265 r180 top
R431 "R-0402_R0402_NC/10K" ASSEMBLY_TOP#3 4400,2850 r270 top
R434 "R-0402_R0402_10K" ASSEMBLY_TOP#3 4727,1578 r180 top
R435 "R-0402_R0402_10K" ASSEMBLY_TOP#3 4720,1690 r180 top
R436 "R-0402_R0402_10K" ASSEMBLY_TOP#3 4720,1730 r180 top
R437 "R-0402_R0402_10K" ASSEMBLY_TOP#3 4180,1599 r180 top
R438 "R-0402_R0402_10K" ASSEMBLY_TOP#3 4180,1559 r180 top
R439 "R-0402_R0402_10K" ASSEMBLY_TOP#3 4560,1465 r270 top
R440 "R-0402_R0402_10K" ASSEMBLY_TOP#3 4520,2145 r90 top
R441 "R-0402_R0402_10K" DISPLAY_TOP#3 3675,1960 r90 top
R442 "R-0402_R0402_10K" DISPLAY_TOP#3 3635,1960 r90 top
R443 "R-0402_R0402_10K" DISPLAY_TOP#3 365,1540 r90 top
R444 "R-0402_R0402_NC/10K" DISPLAY_BOTTOM#1 210,2465 r0 bottom
R445 "R-0402_R0402_10K" DISPLAY_TOP#3 3625,2685 r0 top
R446 "R-0402_R0402_NC/10K" DISPLAY_TOP#3 4131,738 r90 top
R447 "R-0402_R0402_10K" ASSEMBLY_TOP#3 4785,2890 r180 top
R448 "R-0402_R0402_10K" DISPLAY_TOP#3 525,1365 r180 top
R449 "R-0402_R0402_10K" DISPLAY_TOP#3 425,1205 r180 top
R450 "R-0402_R0402_10K" DISPLAY_TOP#3 4990,2275 r0 top
R451 "R-0402_R0402_10K" DISPLAY_TOP#3 4950,1855 r0 top
R452 "R-0402_R0402_1K" DISPLAY_TOP#3 3625,2340 r0 top
R453 "R-0402_R0402_1K" DISPLAY_TOP#3 370,1710 r0 top
R454 "R-0402_R0402_1K" DISPLAY_TOP#3 4171,738 r270 top
R455 "R-0402_R0402_1K" ASSEMBLY_TOP#3 4870,2810 r180 top
R456 "R-0402_R0402_1K" DISPLAY_TOP#3 3625,2565 r180 top
R459 "R-0402_R0402_10K" ASSEMBLY_BOTTOM#1 5200,590 r90 bottom
R460 "R-0402_R0402_0R" ASSEMBLY_BOTTOM#1 5080,475 r90 bottom
R461 "R-0603_R0603_NC/60.4R" ASSEMBLY_BOTTOM#6 5030,590 r90 bottom
R462 "R-0603_R0603_NC/60.4R" ASSEMBLY_BOTTOM#6 5155,590 r90 bottom
R463 "R-0402_R0402_0R" ASSEMBLY_TOP#3 4980,1605 r180 top
R464 "R-0402_R0402_100R" ASSEMBLY_TOP#3 4980,1685 r0 top
R465 "R-0402_R0402_100R" ASSEMBLY_BOTTOM#1 4980,3255 r90 bottom
R466 "R-0402_R0402_100R" ASSEMBLY_TOP#3 4600,2740 r90 top
R782 "R-0402_R0402_47K" DISPLAY_TOP#3 865,2155 r0 top
R783 "R-0402_R0402_100K" DISPLAY_TOP#3 865,2120 r0 top
R785 "R-0402_R0402_10K" DISPLAY_TOP#3 865,2190 r0 top
R787 "R-0402_R0402_73.2K" DISPLAY_TOP#3 770,2195 r90 top
R1060 "R-0402_R0402_10K" DISPLAY_TOP#3 790,2260 r180 top
R1061 "R-0402_R0402_1K" DISPLAY_TOP#3 805,2195 r90 top
R1062 "R-0402_R0402_10K" DISPLAY_TOP#3 690,1625 r0 top
R1063 "R-0402_R0402_100K" DISPLAY_TOP#3 925,1610 r0 top
R1064 "R-0805_R0805_NC/0R" DISPLAY_BOTTOM#10 2775,2075 r270 bottom
R1065 "R-0402_R0402_4.7K" DISPLAY_TOP#3 970,600 r0 top
R1066 "R-0402_R0402_49.9K" DISPLAY_TOP#3 970,465 r180 top
R1067 "R-0402_R0402_20K" DISPLAY_TOP#3 970,505 r0 top
R1068 "R-0402_R0402_4.7K" DISPLAY_TOP#3 1265,510 r0 top
R1069 "R-0402_R0402_49.9K" DISPLAY_TOP#3 1265,375 r180 top
R1070 "R-0402_R0402_20K" DISPLAY_TOP#3 1265,415 r0 top
R1077 "R-0402_R0402_NC/0R" DISPLAY_TOP#3 4895,320 r270 top
R1078 "R-0402_R0402_1K" DISPLAY_TOP#3 1255,1030 r90 top
R1079 "R-0402_R0402_10K" DISPLAY_TOP#3 1240,1200 r180 top
R1080 "R-0402_R0402_100K" DISPLAY_TOP#3 1285,1270 r180 top
R1082 "R-0402_R0402_NC/0R" DISPLAY_TOP#3 1650,2670 r270 top
R1083 "R-0402_R0402_NC/1K" DISPLAY_TOP#3 1305,1370 r270 top
R1084 "R-0603_R0603_NC/0R" DISPLAY_TOP#14 1110,1110 r270 top
R1166 "R-0402_R0402_22R" DISPLAY_TOP#3 4395,445 r180 top
R1167 "R-0402_R0402_22R" DISPLAY_TOP#3 4395,505 r180 top
R1168 "R-0402_R0402_10K" ASSEMBLY_TOP#3 4195,2750 r0 top
R1169 "R-0402_R0402_10K" DISPLAY_TOP#3 4165,990 r180 top
R1170 "R-0402_R0402_45.3K" DISPLAY_TOP#3 4165,950 r0 top
R1171 "R-0402_R0402_22R" DISPLAY_TOP#3 4165,1070 r180 top
R1172 "R-0402_R0402_NC/0R" DISPLAY_TOP#3 1265,550 r180 top
R1173 "R-0402_R0402_0R" DISPLAY_TOP#3 2925,3250 r270 top
R1174 "R-0402_R0402_10K" DISPLAY_TOP#3 5045,925 r0 top
R1175 "RN_0402X4_RN_0402X4_NC/22R" DISPLAY_BOTTOM#8 1800,375 r270 bottom
R1176 "RN_0402X4_RN_0402X4_22R" DISPLAY_TOP#15 1800,375 r270 top
R1177 "R-0402_R0402_120R" DISPLAY_TOP#3 825,460 r90 top
R1178 "R-0402_R0402_120R" DISPLAY_TOP#3 1705,455 r90 top
R1179 "R-0402_R0402_100R" DISPLAY_TOP#3 825,380 r90 top
R1180 "R-0402_R0402_100R" DISPLAY_TOP#3 1670,455 r270 top
R1181 "R-0402_R0402_1K" DISPLAY_TOP#3 745,595 r0 top
R1182 "R-0402_R0402_0R" DISPLAY_TOP#3 345,2140 r90 top
R1183 "R-0402_R0402_0R" DISPLAY_TOP#3 380,2140 r90 top
R1184 "R-0402_R0402_0R" DISPLAY_TOP#3 360,2215 r180 top
R1185 "R-0402_R0402_0R" DISPLAY_TOP#3 360,2250 r180 top
R1186 "R-0402_R0402_0R" DISPLAY_TOP#3 360,2285 r180 top
R1187 "R-0402_R0402_0R" DISPLAY_TOP#3 360,2320 r180 top
R1188 "R-0402_R0402_0R" DISPLAY_TOP#3 360,2355 r180 top
R1189 "R-0402_R0402_0R" DISPLAY_TOP#3 360,2390 r180 top
R1190 "R-0402_R0402_0R" DISPLAY_TOP#3 360,2425 r180 top
R1191 "R-0402_R0402_0R" DISPLAY_TOP#3 360,2460 r180 top
R1192 "R-0402_R0402_10K" DISPLAY_TOP#3 1295,1030 r90 top
R1197 "R-0402_R0402_0R" DISPLAY_TOP#3 425,1365 r180 top
R1198 "R-0402_R0402_4.7K" DISPLAY_TOP#16 1145,2105 r0 bottom
R1200 "R-0402_R0402_10K" DISPLAY_TOP#3 1305,2085 r270 top
R1201 "R-0402_R0402_10K" DISPLAY_TOP#3 4171,813 r90 top
R1202 "R-0603_R0603_NC/0R" DISPLAY_TOP#14 3420,2435 r90 top
R1203 "R-0402_R0402_0R" DISPLAY_TOP#3 3440,1720 r0 bottom
R1204 "R-0402_R0402_0R" DISPLAY_TOP#3 3440,1755 r0 bottom
R1205 "R-0402_R0402_0R" DISPLAY_TOP#3 3440,1685 r0 bottom
R1206 "R-0402_R0402_0R" DISPLAY_TOP#3 3440,1650 r0 bottom
R1207 "R-0402_R0402_NC/22R" ASSEMBLY_TOP#3 4530,475 r0 top
R1208 "R-0402_R0402_NC/22R" ASSEMBLY_TOP#3 4530,510 r0 top
R1209 "R-0603_R0603_0R" ASSEMBLY_TOP#25 3500,935 r90 top
R1210 "R-0603_R0603_0R" ASSEMBLY_TOP#25 3550,935 r90 top
R1211 "R-0402_R0402_10K" ASSEMBLY_TOP#3 4785,1245 r270 top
